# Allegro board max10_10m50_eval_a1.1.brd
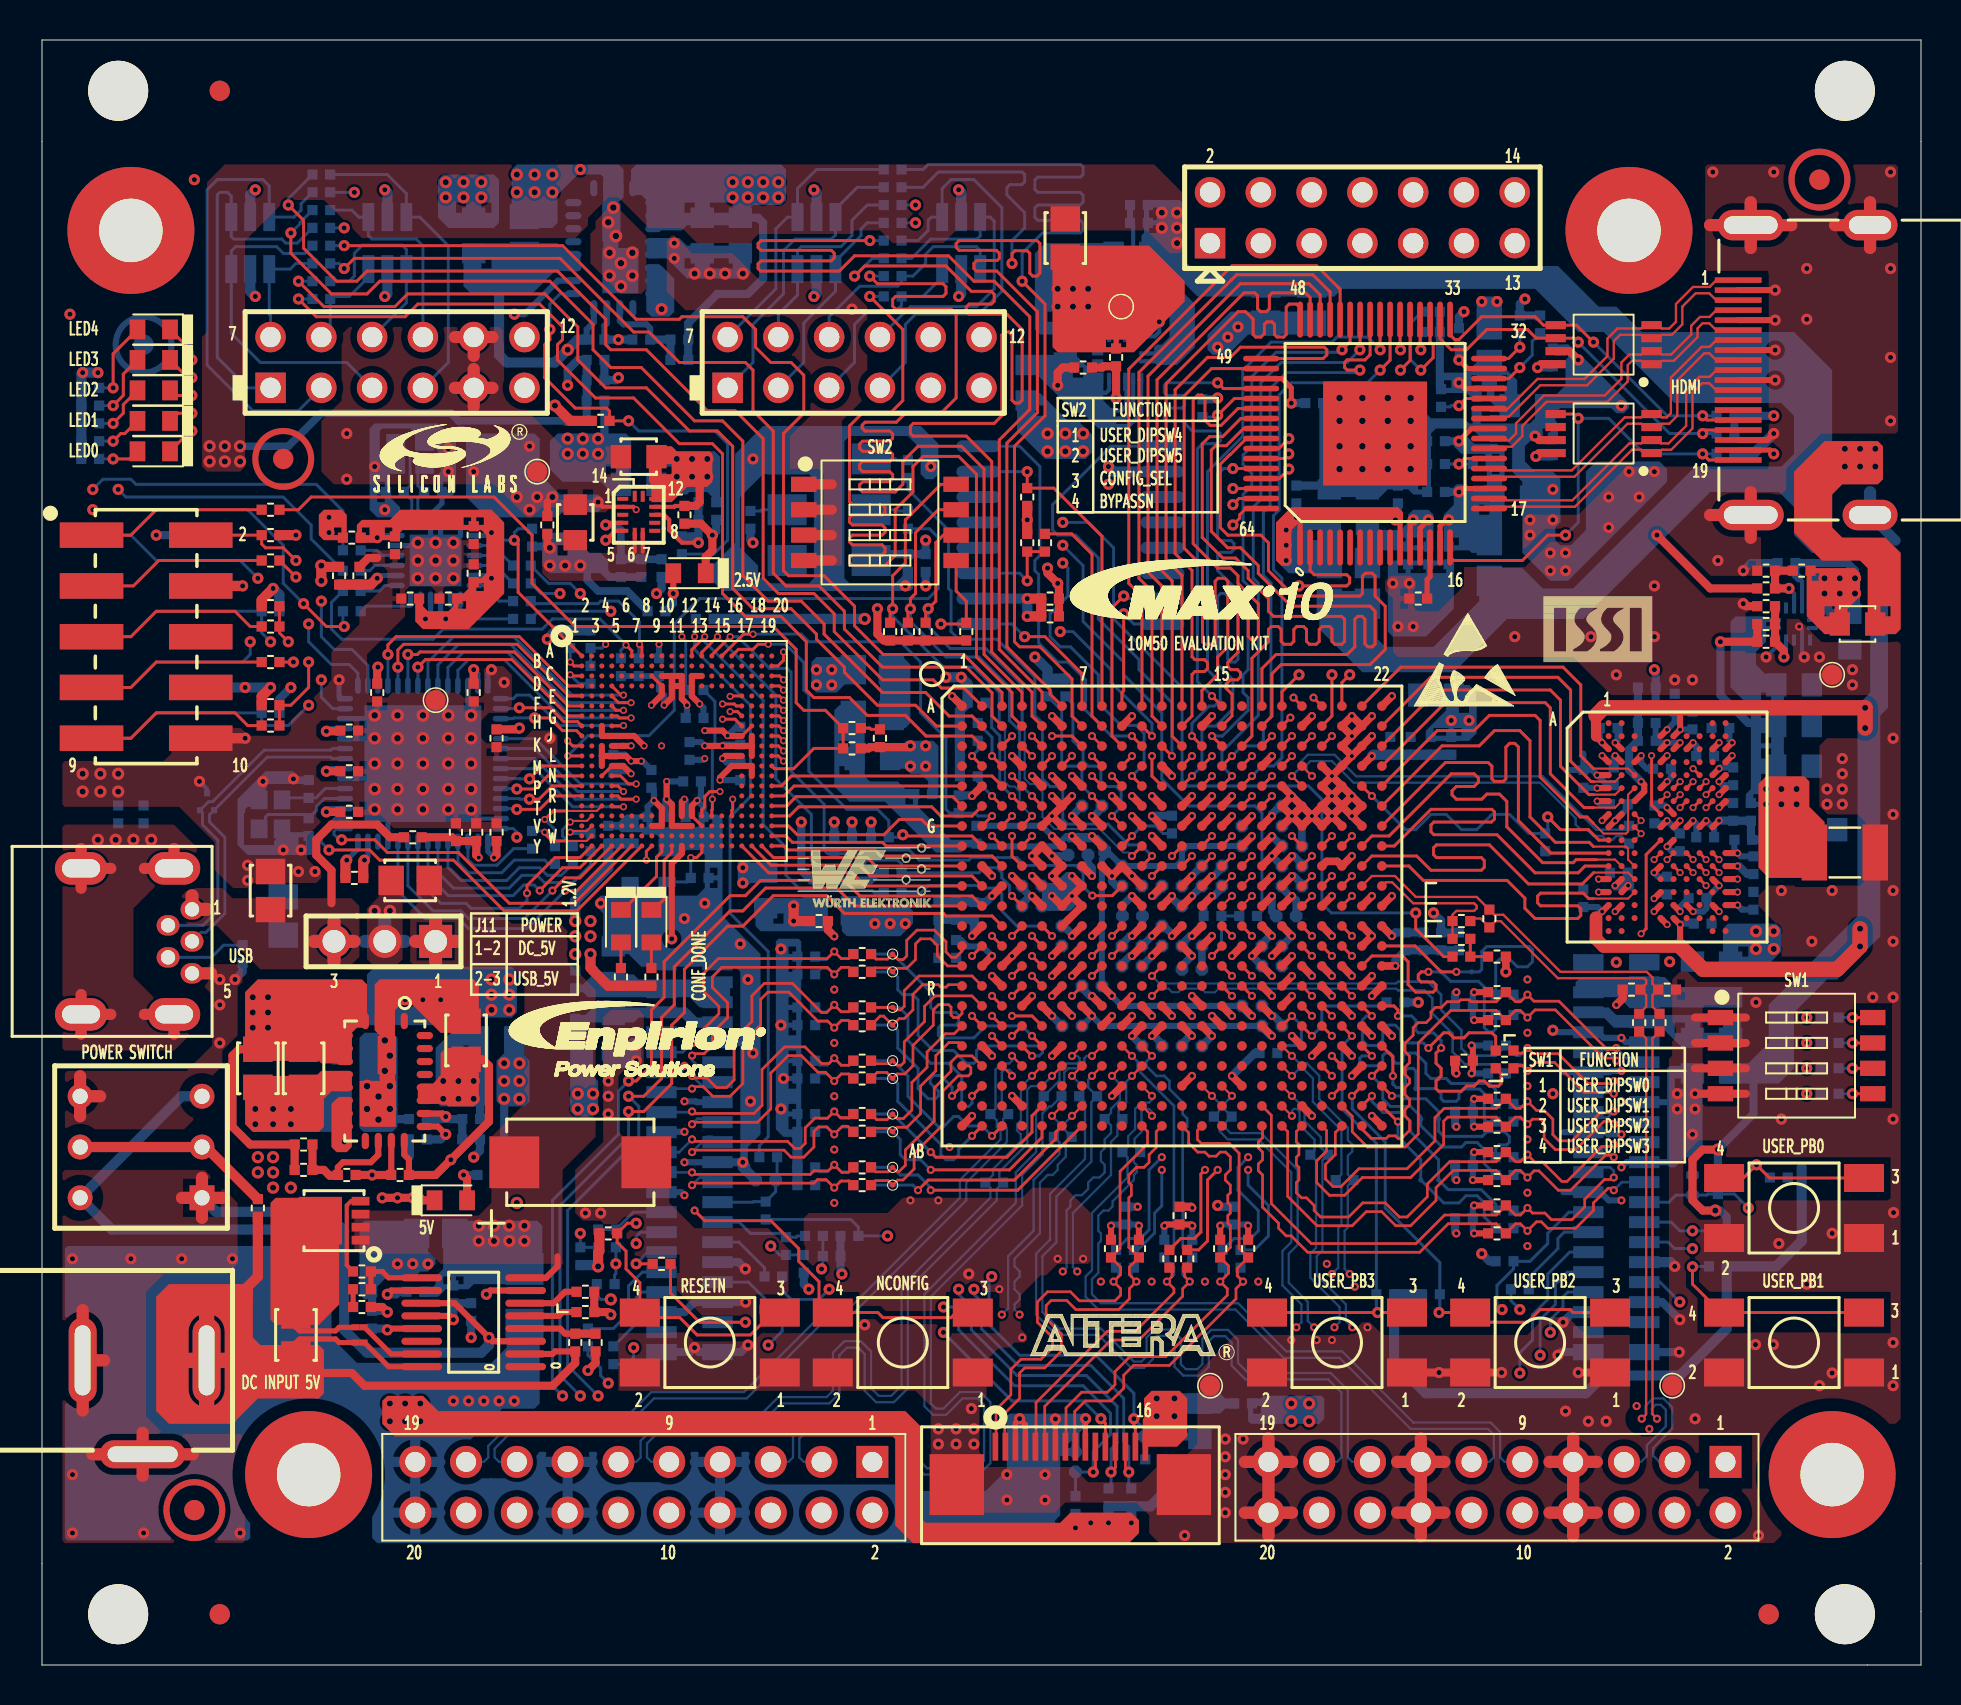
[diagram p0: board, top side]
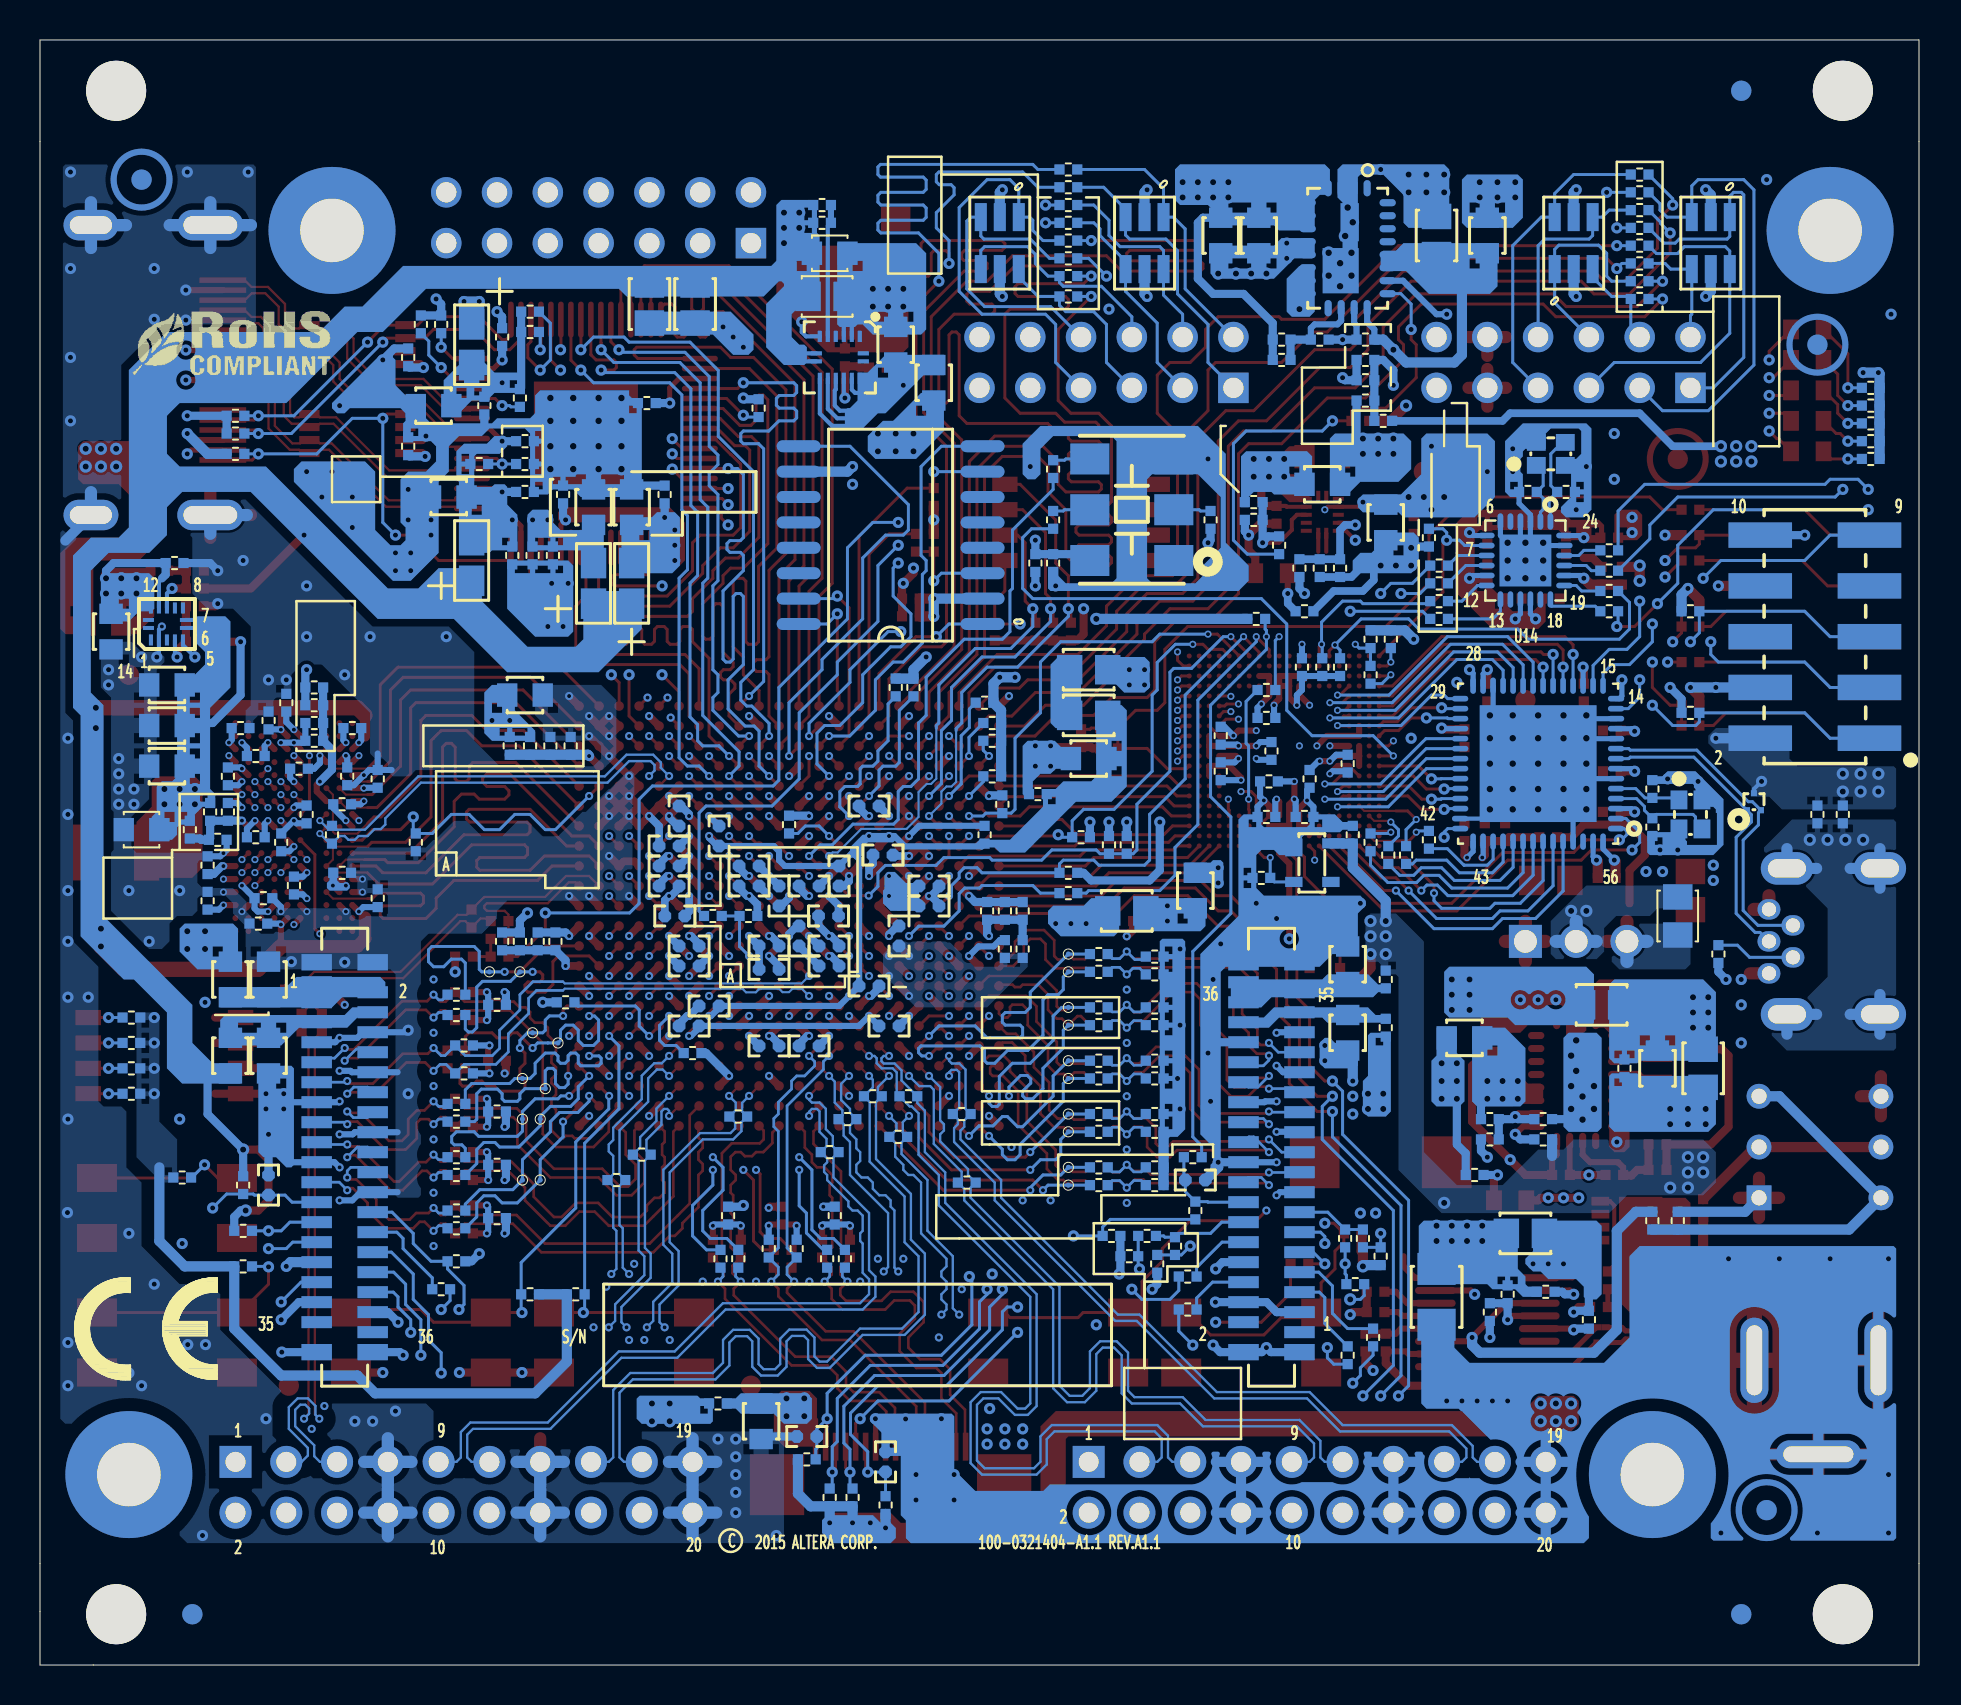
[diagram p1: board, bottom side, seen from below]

Outline 93.98 x 81.28 mm; copper layers: TOP, GND02, VCC03, ART04, GND05, BOTTOM. Coordinates in mm from the lower left corner of the outline.
Outline path: 0,81.28 0,0 93.98,0 93.98,81.28 0,81.28

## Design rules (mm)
net group DIFFPAIR48: nets USER_CLKIN_IO_N USER_CLKIN_IO_P
net group DP_FX2_D_: nets FX2_D_N FX2_D_P
net group MIPI_TX_CLKN: nets MIPI_TX_CLK_HS_N MIPI_TX_CLKN
net group MIPI_TX_CLKP: nets MIPI_TX_CLK_HS_P MIPI_TX_CLKP
net group MIPI_TX_DATA1N: nets MIPI_TX_DATA1N MIPI_TX_DATA_HS_N1
net group MIPI_TX_DATA1P: nets MIPI_TX_DATA1P MIPI_TX_DATA_HS_P1
net group MIPI_TX_DATA2N: nets MIPI_TX_DATA2N MIPI_TX_DATA_HS_N2
net group MIPI_TX_DATA2P: nets MIPI_TX_DATA2P MIPI_TX_DATA_HS_P2
net group MIPI_TX_DATA3N: nets MIPI_TX_DATA3N MIPI_TX_DATA_HS_N3
net group MIPI_TX_DATA3P: nets MIPI_TX_DATA3P MIPI_TX_DATA_HS_P3
net group MIPI_TX_DATA4N: nets MIPI_TX_DATA4N MIPI_TX_DATA_HS_N4
net group MIPI_TX_DATA4P: nets MIPI_TX_DATA4P MIPI_TX_DATA_HS_P4
net group OV10640_HS: nets OV10640_CLK_HS_N OV10640_CLK_HS_P
net group PMODA_D0: nets PMODA_D0 PMODA_IO0
net group PMODA_D1: nets PMODA_D1 PMODA_IO1
net group PMODA_D2: nets PMODA_D2 PMODA_IO2
net group PMODA_D3: nets PMODA_D3 PMODA_IO3
net group PMODA_D4: nets PMODA_D4 PMODA_IO4
net group PMODA_D5: nets PMODA_D5 PMODA_IO5
net group PMODA_D6: nets PMODA_D6 PMODA_IO6
net group PMODA_D7: nets PMODA_D7 PMODA_IO7
net group PMODB_D0: nets PMODB_D0 PMODB_IO0
net group PMODB_D1: nets PMODB_D1 PMODB_IO1
net group PMODB_D2: nets PMODB_D2 PMODB_IO2
net group PMODB_D3: nets PMODB_D3 PMODB_IO3
net group PMODB_D4: nets PMODB_D4 PMODB_IO4
net group PMODB_D5: nets PMODB_D5 PMODB_IO5
net group PMODB_D6: nets PMODB_D6 PMODB_IO6
net group PMODB_D7: nets PMODB_D7 PMODB_IO7
net group LVDS: nets USER_CLKIN_N_MAX10 USER_CLKIN_P USER_CLKIN_P_MAX10
net group OV10640_LP: nets OV10640_CLK_LP_N
net group TMDS: nets TMDS_CLK_N
net group VCC-GND: nets 1.2V_CORE 1.2V_CORE_SENSE 1.2V_VCCIO 3.3V_OV5640 5V 5V_MONITOR 5V_R1.2CORE 5V_R1.2VCCIO 5V_R2.5 5V_R3.3
nets with their own width: min track width 0.203; nets GND
nets with their own width: min track width 0.508; nets 3.3V

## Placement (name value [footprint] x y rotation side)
C1  0.1uF  [0402]  46.61 37.72 0 bottom
C3  0.1uF  [0402]  45.72 37.72 0 bottom
C4  0.1uF  [0402]  69.98 36.2 180 bottom
C6  0.1uF  [0402]  69.47 45.97 180 bottom
C8  0.1uF  [0402]  68.2 36.2 0 bottom
C9  0.1uF  [0402]  67.44 45.97 0 bottom
C10  0.1uF  [0402]  80.26 46.23 270 bottom
C11  0.1uF  [0402]  84.58 42.67 0 bottom
C13  10uF  [0603]  69.72 48.51 180 bottom
C14  4.7UF  [0402]  85.6 38.23 0 bottom
C15  0.1uF  [0402]  85.6 40 0 bottom
C16  0.1uF  [0402]  82.8 38.35 90 bottom
C17  0.1uF  [0402]  80.64 42.55 180 bottom
C18  22nF  [0402]  81.66 48.13 0 bottom
C19  22nF  [0402]  78.61 44.45 180 bottom
C20  0.01uF  [0402]  81.28 38.99 0 bottom
C21  0.01uF  [0402]  83.19 45.47 270 bottom
C22  4.7nF  [0402]  83.19 41.4 270 bottom
C23  4.7nF  [0402]  78.87 43.05 270 bottom
C24  2200pF  [0402]  78.87 39.62 90 bottom
C25  2200pF  [0402]  81.92 41.15 0 bottom
C26  4.7UF  [0402]  82.55 47.24 0 bottom
C27  0.1uF  [0402]  78.36 46.86 270 bottom
C28  DNI  [C0402_BGA]  36.2 24.26 180 bottom
C29  DNI  [0603]  28.57 31.62 270 bottom
C30  DNI  [0603]  28.57 35.05 90 bottom
C31  100 pF  [0402]  71.12 30.23 270 top
C32  100 pF  [0402]  71.12 25.02 90 bottom
C33  100 pF  [0402]  71.12 33.02 90 bottom
C34  100 pF  [0402]  71.12 22.35 90 bottom
C35  100 pF  [0402]  71.12 27.69 90 bottom
C36  DNI  [C0402_BGA]  82.55 24 90 bottom
C37  100 pF  [0402]  56.9 22.48 180 top
C38  DNI  [C0402_BGA]  51.69 10.16 90 bottom
C39  DNI  [C0402_BGA]  55.63 11.43 0 bottom
C40  100 pF  [0402]  59.56 22.48 0 bottom
C41  100 pF  [0402]  54.23 22.48 0 bottom
C42  0.1uF  [0402]  75.56 60.96 0 bottom
C43  0.1uF  [0402]  75.56 65.41 0 bottom
C44  10uF  [0603]  64.39 57.91 90 bottom
C45  0.1uF  [0402]  62.74 58.55 0 bottom
C46  0.1uF  [0402]  63.63 63.12 270 bottom
C47  0.1uF  [0402]  67.82 58.55 0 bottom
C48  0.1uF  [0402]  70.87 66.42 0 bottom
C49  10uF  [0603]  66.29 57.91 90 bottom
C50  0.1uF  [0402]  68.33 55.5 180 bottom
C51  0.1uF  [0402]  69.34 55.5 180 bottom
C52  10uF  [0603]  73.53 58.42 0 bottom
C53  0.1uF  [0402]  70.36 55.5 180 bottom
C54  0.1uF  [0402]  69.72 58.67 90 bottom
C55  0.1uF  [0402]  69.72 61.21 90 bottom
C56  10uF  [0603]  74.3 62.99 0 bottom
C57  0.1uF  [0402]  71.75 62.99 180 bottom
C58  0.1uF  [0402]  28.32 41.53 180 bottom
C59  4.7nF  [0402]  5.08 42.55 0 bottom
C60  12pF  [0402]  13.34 43.81 0 bottom
C61  12pF  [0402]  13.34 41.91 180 bottom
C62  0.1uF  [0402]  21.72 41.66 180 top
C63  0.1uF  [0402]  15.62 39.37 270 top
C64  0.1uF  [0402]  16.76 48.64 0 top
C65  0.1uF  [0402]  21.59 48.64 0 top
C66  0.1uF  [0402]  15.37 42.67 90 top
C67  0.1uF  [0402]  15.37 44.7 90 top
C68  0.1uF  [0402]  22.73 46.35 0 top
C69  0.1uF  [0402]  22.73 41.66 180 top
C70  0.1uF  [0402]  15.37 46.74 90 top
C71  DNI  [0402]  41.91 46.35 0 top
C72  0.1uF  [0402]  30.86 49.91 0 bottom
C73  0.1uF  [0402]  34.92 44.7 180 bottom
C74  0.1uF  [0402]  32.38 45.72 180 bottom
C75  0.1uF  [0402]  32.51 44.2 270 bottom
C76  0.1uF  [0402]  32.64 47.37 270 bottom
C77  0.1uF  [0402]  32.64 42.42 270 bottom
C78  0.1uF  [0402]  30.48 44.32 180 bottom
C79  0.1uF  [0402]  28.57 45.09 180 bottom
C80  0.1uF  [0402]  30.73 42.42 90 bottom
C81  0.1uF  [0402]  34.92 46.48 0 bottom
C82  0.1uF  [0402]  17.65 56.01 0 top
C83  0.1uF  [0402]  18.41 53.34 270 top
C84  0.1uF  [0402]  21.59 56.52 0 top
C85  0.1uF  [0402]  21.59 54.61 180 top
C86  0.1uF  [0402]  20.32 53.34 270 top
C87  DNI  [0402]  17.65 58.67 270 bottom
C88  0.1uF  [0402]  15.88 54.48 180 top
C89  DNI  [0402]  19.56 58.67 90 bottom
C90  22uF  [0805]  24.13 71.5 90 bottom
C91  6.8pF  [0402]  31.88 66.29 90 bottom
C92  22uF  [0603]  34.92 71.5 270 bottom
C93  22uF  [0603]  33.02 71.5 270 bottom
C94  150uF  [7343P]  26.92 25.15 0 top
C95  22uF  [1206]  24.13 18.41 90 bottom
C96  1.0UF  [0402]  27.69 66.29 270 bottom
C97  0.1uF  [0402]  27.18 17.65 90 top
C98  0.01uF  [0402]  16 17.91 270 top
C99  0.1uF  [0402]  27.18 18.67 90 top
C104  2.2uF  [0603]  51.18 66.04 90 bottom
C105  DNI  [0402]  54.86 72.14 90 bottom
C106  10uF  [0805]  54.61 68.45 180 bottom
C107  10uF  [0603]  54.48 70.61 180 bottom
C108  10uF  [0603]  41.53 45.34 0 bottom
C109  0.1uF  [0402]  44.07 43.56 270 bottom
C111  22uF  [0805]  21.21 31.24 90 top
C112  15pF  [0402]  13.08 24.77 270 top
C113  47uF  [0805]  13.08 29.84 270 top
C114  47uF  [0805]  10.79 29.84 270 top
C115  2.2uF  [0603]  90.42 51.69 270 bottom
C116  DNI  [0805]  10.79 29.84 270 bottom
C118  10uF  [0603]  87.63 49.02 0 bottom
C119  DNI  [0402]  86.23 54.74 270 top
C120  1.0UF  [0402]  17.91 24.51 270 top
C121  10uF  [0603]  36.2 38.73 90 bottom
C122  0.1uF  [0402]  38.86 37.21 90 top
C124  0.1uF  [C0402_BGA]  52.51 33.97 0 bottom
C144  0.1uF  [C0402_BGA]  57.51 30.97 180 bottom
C145  0.1uF  [C0402_BGA]  51.51 31.97 0 bottom
C146  0.1uF  [C0402_BGA]  52.51 42.97 180 bottom
C147  0.1uF  [C0402_BGA]  62.01 42.47 90 bottom
C148  0.1uF  [C0402_BGA]  61.51 31.97 180 bottom
C149  0.1uF  [C0402_BGA]  61.51 34.97 180 bottom
C155  0.1uF  [C0402_BGA]  49.51 38.97 0 bottom
C156  0.1uF  [C0402_BGA]  49.51 37.97 0 bottom
C169  4.7UF  [0402]  50.42 52.45 270 top
C170  0.1uF  [0402]  50.42 53.34 90 top
C171  10uF  [0603]  82.55 30.48 270 bottom
C172  10uF  [0603]  82.55 34.29 90 bottom
C173  10uF  [0603]  57.91 12.19 270 bottom
C174  DNI  [0402]  18.8 27.3 90 bottom
C175  DNI  [0402]  33.27 57.28 270 bottom
C176  DNI  [0402]  53.72 65.41 180 top
C194  1.0UF  [C0402_BGA]  61.51 35.97 180 bottom
C196  4.7uF  [C0402_BGA]  51.01 36.46 90 bottom
C197  0.22uF  [0402]  45.72 35.81 0 bottom
C206  0.1uF  [C0402_BGA]  60.01 41.47 270 bottom
C207  DNI  [0402]  27.69 65.28 270 bottom
C208  5 pF  [0402]  86.23 52.07 270 top
C209  2.2uF  [0603]  87.63 46.99 0 bottom
C210  0.1uF  [0402]  87.25 55.12 270 bottom
C211  2.2uF  [0603]  26.67 57.15 90 bottom
C212  0.1uF  [0402]  32.13 57.53 180 top
C213  10uF  [0603]  26.67 57.15 90 top
C215  2.2uF  [0603]  29.84 60.44 180 top
C216  5 pF  [0402]  29.97 54.86 180 bottom
C217  DNI  [0805]  61.21 68.07 270 bottom
C218  DNI  [0805]  63.5 68.07 270 bottom
C219  47uF  [0805]  51.18 71.37 270 top
C220  47uF  [0805]  11.43 38.73 90 top
C221  1.0UF  [C0402_BGA]  57.51 34.8 0 bottom
C222  1.0UF  [C0402_BGA]  54.54 37.46 0 bottom
C223  1.0UF  [C0402_BGA]  51.82 40.51 180 bottom
C224  0.1uF  [C0402_BGA]  56.01 36.47 90 bottom
C225  0.1uF  [C0402_BGA]  54.51 34.97 180 bottom
C226  0.1uF  [C0402_BGA]  57.01 38.47 270 bottom
C227  0.1uF  [C0402_BGA]  55.51 38.97 0 bottom
C228  0.1uF  [C0402_BGA]  54.51 35.97 0 bottom
C229  0.1uF  [C0402_BGA]  57.51 35.97 180 bottom
C230  0.1uF  [C0402_BGA]  58.51 39.97 0 bottom
C231  0.1uF  [C0402_BGA]  58.51 38.97 180 bottom
C232  DNI  [1210]  90.17 40.64 0 top
C233  0.1uF  [C0402_BGA]  62.51 40.97 180 bottom
C234  0.1uF  [C0402_BGA]  62.23 37.46 180 bottom
C235  0.1uF  [C0402_BGA]  62.51 39.97 0 bottom
C236  0.1uF  [C0402_BGA]  62.51 38.97 0 bottom
C237  0.1uF  [C0402_BGA]  60.51 32.97 180 bottom
C238  0.1uF  [C0402_BGA]  54.01 39.47 90 bottom
C239  0.1uF  [C0402_BGA]  55.51 30.97 0 bottom
C240  0.1uF  [0402]  43.31 55.12 180 bottom
C241  0.1uF  [0402]  80.26 48.01 90 bottom
C242  0.1uF  [0402]  86.49 41.78 180 bottom
C243  0.1uF  [0402]  77.09 38.35 0 bottom
C244  0.1uF  [0402]  83.95 46.86 90 bottom
C245  0.1uF  [0402]  84.58 44.45 180 bottom
C246  0.1uF  [0402]  77.09 44.32 0 bottom
C247  0.1uF  [0402]  83.06 37.08 270 bottom
C248  DNI  [0603]  13.08 29.84 270 bottom
C249  DNI  [0402]  14.73 29.84 180 bottom
C250  2.2uF  [0603]  87.63 44.96 0 bottom
C251  2.2uF  [0402]  25.27 57.02 180 top
D1  82401646  [WURTH_MSOP8]  78.11 61.59 180 top
D2  82401646  [WURTH_MSOP8]  78.11 66.04 180 top
D3  GREEN_LED  [LED_0603]  5.59 60.71 0 top
D4  GREEN_LED  [LED_0603]  5.59 62.23 0 top
D5  GREEN_LED  [LED_0603]  5.59 63.75 0 top
D6  GREEN_LED  [LED_0603]  5.59 65.28 0 top
D7  GREEN_LED  [LED_0603]  5.59 66.8 0 top
D8  GREEN_LED  [LED_0603]  30.48 36.96 90 top
D9  YELLOW_LED  [LED_0603]  20.45 23.24 180 top
D10  YELLOW_LED  [LED_0603]  32.38 54.61 0 top
D11  YELLOW_LED  [LED_0603]  28.96 36.96 90 top
J1  FFC_CONN_1x36  [52559-3652]  32.38 25.4 90 bottom
J2  FFC_CONN_1x36  [52559-3652]  78.74 25.4 270 bottom
J3  FFC CONN 1x16  [68711614522]  51.44 10.92 0 top
J4  685119134923  [HDMI-19PIN]  84.84 64.77 180 top
J5  USB MINI-B  [WURTH_USB_MINI-B]  6.6 36.2 270 top
J6  DNI  [HDR2X5_100MIL_SMT]  5.21 53.98 0 bottom
J7  2X5_100mil  [HDR2X5_100MIL_SMT]  5.21 48.89 0 top
J8  2x6 PMOD Connector  [HDR2X6_100MIL]  34.29 63.88 90 top
J9  2x6 PMOD Connector  [HDR2X6_100MIL]  11.43 63.88 90 top
J10  DC Input Jack 2.0 mm  [JACK-DC_2MM]  2.03 15.24 90 top
J11  HEADER, 1x3-PIN  [CONN_TSW_103_07_L_S]  19.68 36.2 180 top
J12  Header 2x10 (DNI)  [10-89-1201]  84.2 10.16 180 top
J13  Header 2x10 (DNI)  [10-89-1201]  41.53 10.16 180 top
J14  Header 2x7 (DNI)  [10-89-1141]  58.42 71.12 90 top
L1  10uH  [0806]  64.39 54.1 0 bottom
L2  10uH  [0806]  66.29 54.1 0 bottom
L3  10uH  [0806]  72.39 55.24 0 bottom
L4  10uH  [0806]  72.39 66.04 180 bottom
L5  BLM15AG221SN1  [0402]  15.49 56.39 270 top
L6  BLM15AG221SN1  [0402]  14.86 54.48 180 top
L7  742792022  [0805]  41.53 47.5 180 bottom
L8  742792022  [0805]  39.62 37.72 180 bottom
L9  BLM15AG221SN1  [0402]  44.2 55.12 0 bottom
NOREF  -  [unnamed]  8.89 2.54 0 top
NOREF#2  -  [unnamed]  7.62 7.75 0 top
NOREF#3  -  [unnamed#2]  79.38 71.75 0 top
NOREF#4  -  [unnamed#2]  90.17 2.54 0 top
NOREF#5  -  [unnamed#2]  89.53 9.53 0 top
NOREF#6  -  [unnamed#2]  90.17 78.74 0 top
NOREF#7  -  [unnamed#2]  4.45 71.75 0 top
NOREF#8  -  [unnamed]  8.89 78.74 0 top
NOREF#9  -  [unnamed#2]  3.81 2.54 0 top
NOREF#10  -  [unnamed]  86.36 2.54 0 top
NOREF#11  -  [unnamed#2]  3.81 78.74 0 top
NOREF#12  -  [unnamed]  12.06 60.32 0 top
NOREF#13  -  [unnamed#2]  13.34 9.53 0 top
NOREF#14  -  [unnamed]  88.9 74.3 0 top
NOREF#15  -  [unnamed]  5.08 66.04 180 bottom
NOREF#16  -  [unnamed]  86.36 2.54 180 bottom
NOREF#17  -  [unnamed]  7.62 7.75 180 bottom
NOREF#18  -  [unnamed]  8.89 2.54 180 bottom
NOREF#19  -  [unnamed]  88.9 74.3 180 bottom
NOREF#20  -  [unnamed]  8.89 78.74 180 bottom
R1  1.00k  [0402]  44.83 35.81 180 bottom
R2  1.00k  [0402]  44.83 37.72 180 bottom
R7  47.5  [0402]  67.69 33.15 90 bottom
R8  47.5  [0402]  61.34 30.61 270 bottom
R9  1.00k  [0402]  70.87 36.2 0 bottom
R10  1.00k  [0402]  70.48 45.97 0 bottom
R11  1.00k  [0402]  69.09 36.2 180 bottom
R12  1.00k  [0402]  68.45 45.97 180 bottom
R17  200  [0402]  60.33 37.46 270 bottom
R18  100.0  [0402]  58.55 37.46 270 bottom
R19  200  [0402]  70.99 35.43 270 top
R20  100.0  [0402]  72.77 35.43 270 top
R21  10.0K  [0402]  39.62 41.02 180 bottom
R22  DNI  [0402]  40.51 41.02 180 bottom
R23  1.00k  [0402]  45.85 43.05 180 bottom
R24  10.0K  [0402]  41.91 41.4 270 bottom
R25  10.0K  [0402]  42.55 39.62 270 bottom
R27  10.0K  [0402]  51.18 48.89 180 bottom
R28  10.0K  [0402]  50.29 48.89 180 bottom
R29  1.00k  [0402]  80.26 48.89 270 bottom
R30  1.00k  [0402]  85.47 42.67 0 bottom
R31  4.7k  [0402]  75.18 41.15 0 bottom
R32  1.00k  [0402]  80.26 47.12 90 bottom
R33  DNI  [0402]  79.38 41.53 180 bottom
R34  1.00k  [0402]  85.09 41.27 270 bottom
R35  240  [0402]  81.03 44.83 270 bottom
R36  100.0  [0402]  41.02 26.67 270 bottom
R37  100.0  [0402]  41.02 32.89 270 bottom
R38  100.0  [0402]  38.23 32.89 90 bottom
R39  100.0  [0402]  38.23 26.67 90 bottom
R40  150  [0402]  41.02 26.67 90 top
R41  150  [0402]  41.02 32.89 90 top
R42  150  [0402]  41.02 32 90 top
R43  100.0  [0402]  38.23 32 270 bottom
R44  150  [0402]  41.02 27.56 90 top
R45  100.0  [0402]  38.23 27.56 270 bottom
R46  100.0  [0402]  41.02 27.56 270 bottom
R47  100.0  [0402]  41.02 32 270 bottom
R48  100.0  [0402]  41.02 35.56 270 bottom
R49  100.0  [0402]  41.02 24.89 270 bottom
R50  150  [0402]  41.02 35.56 90 top
R51  100.0  [0402]  38.23 35.43 90 bottom
R52  100.0  [0402]  38.23 24.89 90 bottom
R53  150  [0402]  41.02 24.89 90 top
R54  150  [0402]  41.02 34.67 90 top
R55  100.0  [0402]  38.23 34.54 270 bottom
R56  150  [0402]  41.02 24 90 top
R57  100.0  [0402]  38.23 24 270 bottom
R58  100.0  [0402]  41.02 34.67 270 bottom
R59  100.0  [0402]  41.02 24 270 bottom
R60  100.0  [0402]  41.02 30.23 270 bottom
R61  DNI  [0402]  26.67 34.29 180 bottom
R62  150  [0402]  41.02 30.23 90 top
R63  100.0  [0402]  38.23 30.23 90 bottom
R64  DNI  [0402]  26.67 31.88 0 bottom
R65  150  [0402]  41.02 29.34 90 top
R66  100.0  [0402]  38.23 29.34 270 bottom
R67  100.0  [0402]  41.02 29.34 90 bottom
R68  DNI  [0402]  39.5 20.45 90 bottom
R71  100.0  [0402]  73.15 30.73 270 top
R72  100.0  [0402]  73.15 25.4 90 bottom
R73  200  [0402]  72.77 30.99 270 bottom
R74  200  [0402]  72.77 25.65 90 top
R75  200  [0402]  72.77 29.59 90 bottom
R76  200  [0402]  72.77 24.26 270 top
R77  100.0  [0402]  73.15 29.84 270 top
R78  100.0  [0402]  73.15 24.51 90 bottom
R79  100.0  [0402]  73.15 32.51 90 bottom
R80  100.0  [0402]  73.15 22.73 90 bottom
R81  200  [0402]  72.77 32.26 90 top
R82  200  [0402]  72.77 22.99 90 top
R83  200  [0402]  72.77 33.66 270 top
R84  200  [0402]  72.77 21.59 270 top
R85  100.0  [0402]  73.15 21.84 90 bottom
R86  100.0  [0402]  73.15 33.53 90 bottom
R87  100.0  [0402]  73.15 28.07 90 bottom
R88  200  [0402]  72.77 28.32 90 top
R89  2.0K  [0402]  73.15 20.19 270 bottom
R90  200  [0402]  72.77 26.92 270 top
R91  2.0K  [0402]  83.82 24 180 bottom
R92  2.0K  [0402]  83.82 21.72 90 bottom
R93  100.0  [0402]  73.15 27.18 90 bottom
R94  DNI  [0402]  73.91 18.8 90 bottom
R95  100.0  [0402]  57.28 20.32 180 top
R96  200  [0402]  57.53 20.83 180 bottom
R97  200  [0402]  56.13 20.83 0 bottom
R98  DNI  [0402]  51.69 8 0 bottom
R99  DNI  [0402]  55.63 10.29 90 bottom
R100  DNI  [0402]  54.48 8.38 0 bottom
R101  DNI  [0402]  53.34 8.38 0 bottom
R102  100.0  [0402]  56.39 20.32 180 top
R103  100.0  [0402]  59.94 20.32 0 bottom
R104  200  [0402]  60.33 20.83 0 top
R105  200  [0402]  58.93 20.83 180 top
R106  100.0  [0402]  59.05 20.32 0 bottom
R107  100.0  [0402]  54.61 20.32 0 bottom
R108  200  [0402]  54.86 20.83 0 top
R109  200  [0402]  53.47 20.83 180 top
R110  100.0  [0402]  53.72 20.32 0 bottom
R111  0  [0402]  73.91 67.06 180 bottom
R112  0  [0402]  74.93 67.06 180 bottom
R113  DNI  [0402]  58.04 62.86 180 bottom
R114  2.0K  [0402]  84.2 61.59 270 bottom
R115  2.0K  [0402]  84.2 62.48 270 bottom
R116  887  [0402]  68.83 53.34 90 top
R117  10.0K  [0402]  84.2 60.58 270 bottom
R118  2.0K  [0402]  69.72 60.07 90 bottom
R119  DNI  [0402]  72.01 60.07 90 bottom
R120  2.0K  [0402]  69.47 66.67 270 bottom
R121  2.0K  [0402]  69.47 67.69 270 bottom
R122  2.0K  [0402]  69.98 63.37 0 bottom
R123  0  [0402]  27.43 49.53 180 bottom
R124  DNI  [0402]  10.03 35.56 180 bottom
R125  1M  [0402]  3.81 42.55 180 bottom
R126  100K  [0402]  32.89 39.37 270 bottom
R127  2.0K  [0402]  26.42 51.31 180 bottom
R128  2.0K  [0402]  27.43 51.31 180 bottom
R129  0  [0402]  24.51 41.27 180 bottom
R130  0  [0402]  26.54 40.51 180 bottom
R131  0  [0402]  27.43 41.15 180 bottom
R132  0  [0402]  25.65 40.51 180 bottom
R133  10.0K  [0402]  18.54 41.4 90 top
R134  20.0K  [0402]  20.7 41.66 0 top
R135  1.00k  [0402]  11.43 47.62 90 bottom
R136  1.00k  [0402]  11.43 52.7 90 bottom
R137  4.7k  [0402]  28.96 49.91 0 bottom
R138  1.00k  [0402]  46.35 44.45 270 bottom
R139  4.7k  [0402]  29.84 49.91 0 bottom
R140  1.00k  [0402]  46.35 46.23 270 bottom
R141  1.00k  [0402]  46.35 47.12 270 bottom
R142  1.00k  [0402]  46.74 48.13 270 bottom
R143  DNI  [0402]  40.51 46.86 90 top
R144  1.00k  [0402]  40.51 45.85 270 top
R145  1.00k  [0402]  11.43 52.96 270 top
R146  1.00k  [0402]  11.43 48.01 270 top
R147  1.00k  [0402]  11.43 56.52 270 top
R148  22.0  [0402]  11.43 57.78 90 top
R149  22.0  [0402]  11.43 55.24 90 top
R150  22.0  [0402]  11.43 51.94 90 top
R151  22.0  [0402]  11.43 50.16 90 top
R152  22.0  [0402]  11.43 46.99 90 top
R153  DNI  [0402]  54.48 25.65 270 bottom
R154  DNI  [0402]  52.32 28.45 270 bottom
R155  DNI  [0402]  63.88 25.53 270 bottom
R156  200  [0402]  42.55 73.91 90 bottom
R157  200  [0402]  42.55 72.14 90 bottom
R158  200  [0402]  42.55 74.8 270 bottom
R159  200  [0402]  42.55 73.02 270 bottom
R160  200  [0402]  42.55 68.45 270 bottom
R161  200  [0402]  42.55 69.47 90 bottom
R162  DNI  [0402]  59.05 27.43 270 bottom
R163  200  [0402]  42.55 71.25 270 bottom
R164  200  [0402]  42.55 70.36 90 bottom
R165  DNI  [0402]  53.59 27.3 270 bottom
R166  DNI  [0402]  50.55 28.45 270 bottom
R167  DNI  [0402]  47.62 24.13 270 bottom
R168  DNI  [0402]  47.88 27.56 270 bottom
R169  DNI  [0402]  51.05 26.42 270 bottom
R170  DNI  [0402]  65.15 24.26 270 bottom
R171  200  [0402]  13.97 71.88 90 bottom
R172  200  [0402]  13.97 70.1 270 bottom
R173  200  [0402]  13.97 73.66 90 bottom
R174  200  [0402]  13.97 68.33 90 bottom
R175  200  [0402]  13.97 70.99 90 bottom
R176  200  [0402]  13.97 69.22 90 bottom
R177  200  [0402]  13.97 74.55 270 bottom
R178  200  [0402]  13.97 72.77 90 bottom
R179  2.0K  [0402]  79.88 32.13 180 top
R180  1.00k  [0402]  79.5 33.78 90 top
R181  10.0K  [0402]  89.41 32.38 270 bottom
R182  10.0K  [0402]  89.41 31.12 270 bottom
R183  150  [0402]  2.41 60.32 270 bottom
R184  10.0K  [0402]  89.41 29.84 270 bottom
R185  10.0K  [0402]  89.41 28.58 270 bottom
R186  150  [0402]  2.41 61.21 270 bottom
R187  150  [0402]  2.41 62.1 270 bottom
R188  150  [0402]  2.41 62.99 270 bottom
R189  10.0K  [0402]  42.42 51.69 180 top
R190  10.0K  [0402]  43.31 51.69 180 top
R191  10.0K  [0402]  44.2 51.69 180 top
R192  10.0K  [0402]  46.23 51.69 180 top
R193  150  [0402]  2.41 63.88 270 bottom
R194  390  [0402]  30.48 34.42 180 top
R195  10.0K  [0402]  69.47 18.54 270 bottom
R196  10.0K  [0402]  83.82 19.94 90 bottom
R198  10.0K  [0402]  67.18 18.54 90 bottom
R199  1.00k  [0402]  22.23 24.51 90 bottom
R200  150  [0402]  30.73 52.7 90 bottom
R202  10.0K  [0402]  86.87 24.38 90 bottom
R203  10.0K  [0402]  56.52 42.04 180 bottom
R204  10.0K  [0402]  28.32 21.59 90 top
R205  4.7k  [0402]  24.51 56.39 180 bottom
R206  22.0  [0402]  24 53.21 90 bottom
R207  0  [0402]  24 54.99 270 bottom
R208  0  [0402]  24 54.1 270 bottom
R209  22.0  [0402]  15.49 53.72 270 bottom
R210  0  [0402]  24 52.32 270 bottom
R211  0  [0402]  15.49 52.7 90 bottom
R212  DNI  [0402]  15.49 54.74 90 bottom
R213  0  [0402]  15.49 55.75 90 bottom
R214  1.00k  [0402]  35.43 57.28 0 bottom
R215  22.0  [0402]  43.31 59.82 180 bottom
R216  22.0  [0402]  43.31 57.28 180 bottom
R217  40.2K  [0402]  10.79 22.86 180 top
R221  20.0K  [0402]  12.06 22.23 180 bottom
R222  0.005  [0805]  12.7 16.51 270 top
R223  348K  [0402]  31.88 65.28 270 bottom
R224  69.8K  [0402]  26.67 16.13 0 top
R225  10  [0402]  16 19.69 90 top
R226  60.4K  [0402]  20.57 18.54 0 bottom
R227  10.0K  [0402]  18.67 18.67 270 bottom
R228  1K  [0805]  19.68 21.59 180 bottom
R229  78.7K  [0402]  29.97 66.29 270 bottom
R230  20.0K  [0402]  27.69 16.13 180 top
R231  1.00k  [0402]  16 18.8 90 top
R232  20.0K  [0402]  16.51 17.27 180 bottom
R233  20.0K  [0402]  21.46 17.65 0 bottom
R235  0  [0402]  54.86 73.02 90 bottom
R236  0.1  [0805]  41.53 49.78 0 bottom
R238  0.01  [0805]  15.88 33.02 0 bottom
R239  10.0K  [0402]  18.8 26.29 90 bottom
R240  348K  [0402]  13.08 26.03 270 top
R241  DNI  [0402]  86.23 53.85 270 top
R242  0  [0402]  88.01 54.74 90 top
R243  348K  [0402]  15.24 24.51 270 top
R244  2.0K  [0402]  49.28 56.13 0 top
R245  DNI  [0402]  49.28 58.42 180 top
R246  0  [0603]  84.45 30.48 90 bottom
R247  0  [0603]  84.45 34.29 270 bottom
R248  0  [0402]  60.07 13.08 270 bottom
R249  0  [0402]  32.64 48.77 270 bottom
R250  0  [0402]  50.16 56.13 180 top
R252  DNI  [0402]  21.46 27.3 270 bottom
R253  0  [0603]  22.73 31.37 180 bottom
R254  0  [0603]  90.81 52.07 180 top
R255  DNI  [0402]  33.27 58.17 270 bottom
R257  0  [0402]  52.07 64.9 90 top
R258  0  [0603]  49.28 64.14 90 bottom
R260  0  [0603]  21.59 71.5 270 bottom
R264  0  [0402]  13.34 22.23 0 bottom
R267  DNI  [0402]  46.74 41.53 180 bottom
R268  2.0K  [0402]  80.9 32.13 180 top
R269  1.00k  [0402]  81.28 33.78 270 top
R270  0  [0402]  70.99 36.32 270 top
R271  DNI  [0402]  70.99 37.21 270 top
R272  DNI  [0402]  72.39 37.34 0 top
R273  DNI  [0402]  36.58 19.43 90 bottom
R274  DNI  [0402]  30.99 20.07 270 top
R275  DNI  [0402]  27.3 16.38 0 bottom
R276  DNI  [0402]  36.58 17.78 90 bottom
R277  DNI  [0402]  28.57 15.49 0 bottom
R278  390  [0402]  28.96 34.42 180 top
R279  0  [0402]  26.8 62.23 90 bottom
R280  DNI  [0402]  27.69 63.25 270 bottom
R281  10.0K  [0402]  27.94 62.23 270 top
R282  0  [0402]  32 56.01 180 bottom
R283  0  [0402]  21.46 26.29 270 bottom
R284  DNI  [0402]  27.69 64.26 90 bottom
R285  200k  [0402]  86.23 51.18 270 top
R286  200k  [0402]  86.23 52.96 90 top
R289  0  [0603]  29.84 59.05 0 bottom
R290  200k  [0402]  28.96 54.86 180 bottom
R291  63.0K  [0402]  30.99 54.86 0 bottom
R292  DNI  [0805]  18.41 39.24 180 top
R293  DNI  [0805]  12.06 37.46 270 bottom
R294  DNI  [0402]  38.61 21.46 270 bottom
R302  DNI  [0402]  37.21 20.95 180 bottom
R303  DNI  [0402]  38.1 20.07 0 bottom
R304  DNI  [0402]  27.81 21.34 180 bottom
R305  DNI  [0402]  28.19 19.05 270 bottom
R306  DNI  [0402]  26.92 20.45 0 bottom
R307  DNI  [0402]  28.7 21.34 180 bottom
R308  DNI  [0402]  40.39 21.46 270 bottom
R309  DNI  [0402]  33.15 52.32 90 bottom
R312  DNI  [0402]  36.2 22.73 180 bottom
R313  DNI  [0402]  36.32 25.4 90 bottom
R314  22.0  [0402]  42.55 38.61 270 bottom
R315  51  [0603]  88.9 41.78 180 bottom
S1  PB Switch  [PUSHBUTTON_SMT]  87.63 22.86 180 top
S2  PB Switch  [PUSHBUTTON_SMT]  87.63 16.13 180 top
S3  PB Switch  [PUSHBUTTON_SMT]  74.93 16.13 180 top
S4  PB Switch  [PUSHBUTTON_SMT]  64.77 16.13 180 top
S6  PB Switch  [PUSHBUTTON_SMT]  43.05 16.13 180 top
S7  PB Switch  [PUSHBUTTON_SMT]  33.4 16.13 180 top
SW1  DIPSWITCH4  [DIPSWITCH_SMT_QUAD]  87.76 32.38 270 top
SW2  DIPSWITCH4  [DIPSWITCH_SMT_QUAD]  41.91 59.05 270 top
SW3  POWER SW  [SW-PUSH-8X8]  8 23.37 90 top
TP1  T POINT R  [TEST_PAD_SMT]  81.53 13.97 270 top
TP2  T POINT R  [TEST_PAD_SMT]  58.42 13.97 90 top
TP3  T POINT R  [TEST_PAD_SMT]  24.77 59.69 180 top
TP4  T POINT R  [TEST_PAD_SMT]  53.98 67.95 180 top
TP5  T POINT R  [TEST_PAD_SMT]  89.53 49.53 270 top
TP6  T POINT R  [TEST_PAD_SMT]  19.68 48.26 270 top
TP7  T POINT R  [TEST_PAD_SMT_10MIL]  42.55 32.89 180 bottom
TP8  T POINT R  [TEST_PAD_SMT_10MIL]  42.55 32.89 0 top
TP10  T POINT R  [TEST_PAD_SMT_10MIL]  42.55 32 0 top
TP11  T POINT R  [TEST_PAD_SMT_10MIL]  42.55 32 180 bottom
TP13  T POINT R  [TEST_PAD_SMT_10MIL]  42.55 35.56 180 bottom
TP14  T POINT R  [TEST_PAD_SMT_10MIL]  42.55 35.56 0 top
TP15  T POINT R  [TEST_PAD_SMT_10MIL]  42.55 34.67 0 top
TP16  T POINT R  [TEST_PAD_SMT_10MIL]  42.55 34.67 180 bottom
TP19  T POINT R  [TEST_PAD_SMT_10MIL]  42.55 30.23 180 bottom
TP20  T POINT R  [TEST_PAD_SMT_10MIL]  42.55 30.23 0 top
TP21  T POINT R  [TEST_PAD_SMT_10MIL]  42.55 29.34 0 top
TP22  T POINT R  [TEST_PAD_SMT_10MIL]  42.55 29.34 180 bottom
TP25  T POINT R  [TEST_PAD_SMT_10MIL]  42.55 26.67 180 bottom
TP26  T POINT R  [TEST_PAD_SMT_10MIL]  42.55 26.67 0 top
TP27  T POINT R  [TEST_PAD_SMT_10MIL]  42.55 27.56 0 top
TP28  T POINT R  [TEST_PAD_SMT_10MIL]  42.55 27.56 180 bottom
TP31  T POINT R  [TEST_PAD_SMT_10MIL]  42.55 24.89 180 bottom
TP32  T POINT R  [TEST_PAD_SMT_10MIL]  42.55 24.89 0 top
TP33  T POINT R  [TEST_PAD_SMT_10MIL]  42.55 24 0 top
TP34  T POINT R  [TEST_PAD_SMT_10MIL]  42.55 24 180 bottom
TP45  T POINT R  [TEST_PAD_SMT_10MIL]  69.98 34.67 180 bottom
TP48  T POINT R  [TEST_PAD_SMT_10MIL]  71.5 34.67 180 bottom
TP50  T POINT R  [TEST_PAD_SMT_10MIL]  69.85 29.34 180 bottom
TP54  T POINT R  [TEST_PAD_SMT_10MIL]  68.71 28.83 180 bottom
TP57  T POINT R  [TEST_PAD_SMT_10MIL]  69.85 27.3 180 bottom
TP60  T POINT R  [TEST_PAD_SMT_10MIL]  68.96 27.3 180 bottom
TP63  T POINT R  [TEST_PAD_SMT_10MIL]  69.85 24.26 180 bottom
TP66  T POINT R  [TEST_PAD_SMT_10MIL]  68.96 24.26 180 bottom
TP67  T POINT R  [TEST_PAD_SMT_10MIL]  68.07 31.12 180 bottom
TP68  T POINT R  [TEST_PAD_SMT_10MIL]  69.34 31.62 180 bottom
U1  10M50DAF484  [F484]  56.52 37.46 0 top
U2  LPDDR2_IS43LD16640A-3BL  [FBGA134]  81.28 41.91 0 top
U3  ADV7513BSWZ  [LQFP-64]  66.67 61.59 90 top
U4  EPM1270_M256FBGA  [M256]  31.75 45.72 0 top
U5  MAX811  [SOT-143]  30.35 40.13 180 bottom
U6  TPD2EUSB30  [DRT]  8.26 43.18 180 bottom
U7  CY7C68013A_QFN  [QFN56]  19.05 45.09 0 bottom
U8  824013  [SOT23-6L]  45.97 71.12 0 bottom
U9  824013  [SOT23-6L]  38.73 71.12 0 bottom
U10  824013  [SOT23-6L]  10.41 71.12 0 bottom
U11  824013  [SOT23-6L]  17.27 71.12 180 bottom
U14  Si5338C-CUSTOM  [QFN24]  19.68 55.24 270 bottom
U15  510MCA50M0000AAGR  [SI510]  39.37 57.78 90 bottom
U16  FDMC8878  [FDMC8878_VER2]  14.61 22.23 90 top
U17  EN5329QI  [EN5339QI]  28.57 70.87 270 bottom
U18  LTC4218CGN  [16-LEAD_PLASTIC_SSOP]  21.59 17.14 90 top
U19  -  [EP5348UI]  29.84 57.53 0 top
U20  EP5358HUI  [UQFN16]  53.98 65.41 270 bottom
U21  -  [EN5339QI]  17.14 29.21 270 top
U22  -  [EP5348UI]  87.63 52.07 90 bottom
U23  N25Q512A83GSF40F  [SO16_WIDE]  51.44 56.52 90 bottom
V1  SENSE_PAD  [SENSE]  15.88 16.13 270 top
V2  SENSE_PAD  [SENSE]  15.88 16.89 270 top
Y1  24.00MHz  [XTAL_FA-128]  11.43 42.55 270 bottom
Y2  25.00MHz  [XTAL_FA-128]  18.41 60.58 180 bottom

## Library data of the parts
C1 C3 C4 C6 C8-C11 C15-C17 C27 C31-C35 C37 C40-C43 C45-C48 C50 C51 C53-C55 C57 C58 C62-C86 C88 C91 C109 C122 C170 C197 C210 C212 C240-C247 = Cap 0.1UF +/-10% 10V 0402: Tolerance: TOL; User Part Number: PART#
C13 C29 C30 C44 C49 C52 C56 C95 C104 C106-C108 C113-C115 C118 C121 C171-C173 C209 C211 C213 C215 C217-C220 C248 C250 = CAP
C14 C26 C169 = Cap 4.7uF 10% 6.3V X5R 0402: Tolerance: TOL; User Part Number: PART#
C18 C19 = Cap 22NF 10% 16V 0402: Tolerance: TOL; User Part Number: PART#; signal model: CAP_22NF_10%_16V_0402_0402_22NF_22nF
C20 C21 = CAP 0.01UF 16V X7R 0402: Tolerance: TOL; User Part Number: PART#
C22 C23 C59 = Cap 4.7nF 10% 50V 0402: Tolerance: TOL; User Part Number: PART#
C24 C25 = Cap 2200PF 10% 50V 0402: Tolerance: TOL; User Part Number: PART#
C28 C36 C38 C39 C194 C221-C223 = CAP 1.0UF 10% 10V 0402
C60 C61 C97-C99 C105 C112 C208 C216 C251 = CAP: Tolerance: TOL; User Part Number: PART#
C87 C89 = Cap 18PF 5% 50V 0402: Tolerance: TOL; User Part Number: PART#
C90 C92 C93 C111 C116 C124 C144-C149 C155 C156 C206 C224-C231 C233-C239 = Cap 0.1UF +/-10% 10V 0402
C94 = PCAP: User Part Number: PART#; Tolerance: TOL
C96 C119 C120 C174-C176 C207 C249 = CAP 1.0UF 10% 10V 0402: Tolerance: TOL; User Part Number: PART#
C196 = Cap 4.7uF 10% 6.3V X5R 0402
C232 = CAP: User Part Number: *; Tolerance: *
D1 D2 = 82401646: User Part Number: *
D3-D11 = LED_WURTH_1
J1 J2 = FCC CONN_1
J3 = FFC_CONN_0
J4 = HDMI 19-Pin Receptacle: Tolerance: XXX; User Part Number: XXX
J5 = USB MINI-B
J6 J7 = 2x5: User Part Number: *; Tolerance: *
J8 J9 = 2x6 PMOD
J10 = Jack-DC
J11 = HEADER, 1x3-PIN: User Part Number: *
J12 J13 = 2x10
J14 = Header_3
L1-L4 = IND 10uH 245mA 0.82ohm 0806 SMD
L5 L6 L9 = IND Ferrite 0402 300mA/220: Tolerance: TOL; User Part Number: PART#
L7 L8 = INDUCTOR
R1 R2 R7-R12 R17 R19 R21-R25 R27-R30 R32 R34 R35 R61 R64 R94 R111 R112 R117 R123-R126 R129-R136 R138 R140-R152 R180-R182 R184 R185 R189-R192 R195 R196 R198 R199 R202-R204 R206-R217 R221 R223 R227 R229-R233 R235 R239-R243 R248-R250 R255 R257 R264 R267 R269-R271 R273-R277 R279-R286 R290 R291 R294 R302 R304 R307 R312-R314 = RESISTOR: Tolerance: TOL; User Part Number: PART#
R18 R20 R36-R39 R43 R45-R49 R51 R52 R55 R57-R60 R63 R66 R67 R71 R72 R77-R80 R85-R87 R93 R95 R102 R103 R106 R107 R110 R153-R155 R162 R165-R170 R272 = RES 100 OHM 1.0% 1/16W 0402: Tolerance: TOL; User Part Number: PART#
R31 R137 R139 R205 = RES 4.7k OHM 5% 1/16W 0402: Tolerance: TOL; User Part Number: PART#
R33 = RES 4.7k OHM 5% 1/16W 0402: Tolerance: TOL; User Part Number: PART#; signal model: RES_4.7K_OHM_5%_1/16W_0402_04_1_DNI
R40-R42 R44 R50 R53 R54 R56 R62 R65 R183 R186-R188 R193 R200 = R: Tolerance: TOL; User Part Number: PART#; signal model: R_0402_150_150
R68 R89 R91 R92 R98-R101 R114 R115 R118-R122 R127 R128 R179 R244 R245 R268 R303 R305 R306 R308 R309 = RES 2.0K OHM 1/16W 1% 0402 SMD: Tolerance: TOL; User Part Number: PART#
R73-R76 R81-R84 R88 R90 R96 R97 R104 R105 R108 R109 R156-R161 R163 R164 R171-R178 = RESISTOR: Tolerance: TOL; User Part Number: PART#; signal model: RESISTOR_0402_200_200
R113 R116 R194 R278 = R: Tolerance: TOL; User Part Number: PART#
R222 R228 R236 R238 R246 R247 R253 R254 R258 R260 R289 R292 R293 R315 = RESISTOR
R224 R226 = RES 16.5K OHM 1/10W 1% 0402: Tolerance: TOL; User Part Number: PART#
R225 = RES 10 OHM 1.0% 1/16W 0402: Tolerance: TOL; User Part Number: PART#
R252 = RES 30.1K OHM 1% 1/16W 0402 SMD: Tolerance: TOL; User Part Number: PART#
S1-S4 S6 S7 = TS-A02SA-2-S100
SW1 SW2 = SPST4
SW3 = SW-PUSH_3
TP1-TP8 TP10 TP11 TP13-TP16 TP19-TP22 TP25-TP28 TP31-TP34 TP45 TP48 TP50 TP54 TP57 TP60 TP63 TP66-TP68 = T POINT R
U1 = 10M50DAF484_v2.0_4.5
U2 = LPDDR2_IS43LD16640A-3BL_2
U3 = ADV7513BSWZ
U4 = EPM1270M256_2: Tolerance: *; User Part Number: *
U5 = MAX811: User Part Number: PART#; Tolerance: TOL
U6 = TPD2EUSB30: User Part Number: *; Tolerance: *
U7 = CY7C68013A_56QFN: User Part Number: *
U8-U11 = 824013
U14 = Clock Gen, Si5338A_CUSTOM, A5SK: User Part Number: *
U15 = Si510-DualCMOS: Tolerance: ?; User Part Number: XOS006RM01A
U16 = FDMC8878_VER2: User Part Number: *
U17 U21 = EN5329/5339QI_0
U18 = LTC4218CGN
U19 U22 = EP5348UI_0: Tolerance: ?
U20 = EP5358xUI
U23 = N25Q00AA13GSF40F_1
V1 V2 = SENSE_PAD: User Part Number: *
Y1 = CRYSTAL_SM_13: User Part Number: *
Y2 = XTAL 25MHz 30PPM 18pF mini: User Part Number: *

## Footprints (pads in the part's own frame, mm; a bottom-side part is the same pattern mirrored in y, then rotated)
10-89-1141
  rect 1.524x1.524 hole 1.016: 1(0,0)
  round 1.524 hole 1.016: 2(2.54,0) 3(0,-2.54) 4(2.54,-2.54) 5(0,-5.08) 6(2.54,-5.08) 7(0,-7.62) 8(2.54,-7.62) 9(0,-10.16) 10(2.54,-10.16) 11(0,-12.7) 12(2.54,-12.7) 13(0,-15.24) 14(2.54,-15.24)
10-89-1201
  rect 1.6x1.6 hole 1: 1(0,0)
  round 1.6 hole 1: 2(0,2.54) 3(2.54,0) 4(2.54,2.54) 5(5.08,0) 6(5.08,2.54) 7(7.62,0) 8(7.62,2.54) 9(10.16,0) 10(10.16,2.54) 11(12.7,0) 12(12.7,2.54) 13(15.24,0) 14(15.24,2.54) 15(17.78,0) 16(17.78,2.54) 17(20.32,0) 18(20.32,2.54) 19(22.86,0) 20(22.86,2.54)
16-LEAD_PLASTIC_SSOP
  oval 0.356x2.032 smd: 1(-2.223,-2.6) 2(-1.587,-2.6) 3(-0.953,-2.6) 4(-0.318,-2.6) 5(0.318,-2.6) 6(0.953,-2.6) 7(1.587,-2.6) 8(2.223,-2.6) 9(2.223,2.6) 10(1.587,2.6) 11(0.953,2.6) 12(0.318,2.6) 13(-0.318,2.6) 14(-0.953,2.6) 15(-1.587,2.6) 16(-2.223,2.6)
0402
  rect 0.508x0.508 smd: 1(0,0.445) 2(0,-0.445)
0603
  rect 1.016x1.168 smd: 1(-0.889,0) 2(0.889,0)
0805
  rect 1.27x1.473 smd: 1(-0.953,0) 2(0.953,0)
0806
  rect 1.27x1.524 smd: 1(0,1.016) 2(0,-1.016)
1206
  rect 1.6x1.905 smd: 1(-1.397,0) 2(1.397,0)
1210
  rect 1.27x2.794 smd: 1(-1.524,0) 2(1.524,0)
7343P
  rect 2.489x2.591 smd: 1(-3.302,0) 2(3.302,0)
52559-3652
  rect 0.6x1.524 smd: 1(-8.75,-1.4) 2(-8.25,1.4) 3(-7.75,-1.4) 4(-7.25,1.4) 5(-6.75,-1.4) 6(-6.25,1.4) 7(-5.75,-1.4) 8(-5.25,1.4) 9(-4.75,-1.4) 10(-4.25,1.4) 11(-3.75,-1.4) 12(-3.25,1.4) 13(-2.75,-1.4) 14(-2.25,1.4) 15(-1.75,-1.4) 16(-1.25,1.4) 17(-0.75,-1.4) 18(-0.25,1.4) 19(0.25,-1.4) 20(0.75,1.4) 21(1.25,-1.4) 22(1.75,1.4) 23(2.25,-1.4) 24(2.75,1.4) 25(3.25,-1.4) 26(3.75,1.4) 27(4.25,-1.4) 28(4.75,1.4) 29(5.25,-1.4) 30(5.75,1.4) 31(6.25,-1.4) 32(6.75,1.4) 33(7.25,-1.4) 34(7.75,1.4) 35(8.25,-1.4) 36(8.75,1.4)
  rect 0.813x1.524 smd: G1(-9.75,-1.4) G2(9.75,-1.4) G3(9.75,1.4) G4(-9.75,1.4)
68711614522
  rect 0.279x1.397 smd: 1(-3.75,0) 2(-3.25,0) 3(-2.75,0) 4(-2.25,0) 5(-1.75,0) 6(-1.25,0) 7(-0.75,0) 8(-0.25,0) 9(0.25,0) 10(0.75,0) 11(1.25,0) 12(1.75,0) 13(2.25,0) 14(2.75,0) 15(3.25,0) 16(3.75,0)
  rect 2.718x3.048 smd: 17(-5.68,-1.9) 18(5.68,-1.9)
C0402_BGA
  rrect 0.635x0.635 smd: 1(-0.5,0) 2(0.5,0)
CONN_TSW_103_07_L_S
  rect 1.651x1.651 hole 1.143: 1(0,0)
  round 1.651 hole 1.143: 2(2.54,0) 3(5.08,0)
DIPSWITCH_SMT_QUAD
  rect 0.762x1.27 smd: 1(0,-3.81) 2(1.27,-3.81) 3(2.54,-3.81) 4(3.81,-3.81) 5(3.81,3.81) 6(2.54,3.81) 7(1.27,3.81) 8(0,3.81)
DRT
  rect 0.305x0.305 smd: 1(-0.35,-0.425) 2(0.35,-0.425) 3(0,0.425)
EN5339QI
  oval 0.813x0.356 smd: 1(-3,0.975) 2(-3,0.325) 3(-3,-0.325) 4(-3,-0.975) 13(3,-0.975) 14(3,-0.325) 15(3,0.325) 16(3,0.975)
  oval 0.356x0.813 smd: 5(-2.275,-2) 6(-1.625,-2) 7(-0.975,-2) 8(-0.325,-2) 9(0.325,-2) 10(0.975,-2) 11(1.625,-2) 12(2.275,-2) 17(2.275,2) 18(1.625,2) 19(0.975,2) 20(0.325,2) 21(-0.325,2) 22(-0.975,2) 23(-1.625,2) 24(-2.275,2)
  rect 1.905x0.914 smd: 25(-1.3,0.1)
  rect 2.261x1.803 smd: 26(1.125,-0.35)
EP5348UI
  rect 0.55x0.2 smd: 1(-0.8,0.8) 2(-0.8,0.4) 3(-0.8,0) 4(-0.8,-0.4) 5(-0.8,-0.8) 8(0.8,-0.8) 9(0.8,-0.4) 10(0.8,0) 11(0.8,0.4) 12(0.8,0.8)
  rect 0.2x0.55 smd: 6(-0.2,-0.925) 7(0.2,-0.925) 13(0.2,0.925) 14(-0.2,0.925)
F484
  round 0.48 smd: A1(-10.5,10.5) A2(-9.5,10.5) A3(-8.5,10.5) A4(-7.5,10.5) A5(-6.5,10.5) A6(-5.5,10.5) A7(-4.5,10.5) A8(-3.5,10.5) A9(-2.5,10.5) A10(-1.5,10.5) A11(-0.5,10.5) A12(0.5,10.5) A13(1.5,10.5) A14(2.5,10.5) A15(3.5,10.5) A16(4.5,10.5) A17(5.5,10.5) A18(6.5,10.5) A19(7.5,10.5) A20(8.5,10.5) A21(9.5,10.5) A22(10.5,10.5) AA1(-10.5,-9.5) AA2(-9.5,-9.5) AA3(-8.5,-9.5) AA4(-7.5,-9.5) AA5(-6.5,-9.5) AA6(-5.5,-9.5) AA7(-4.5,-9.5) AA8(-3.5,-9.5) AA9(-2.5,-9.5) AA10(-1.5,-9.5) AA11(-0.5,-9.5) AA12(0.5,-9.5) AA13(1.5,-9.5) AA14(2.5,-9.5) AA15(3.5,-9.5) AA16(4.5,-9.5) AA17(5.5,-9.5) AA18(6.5,-9.5) AA19(7.5,-9.5) AA20(8.5,-9.5) AA21(9.5,-9.5) AA22(10.5,-9.5) AB1(-10.5,-10.5) AB2(-9.5,-10.5) AB3(-8.5,-10.5) AB4(-7.5,-10.5) AB5(-6.5,-10.5) AB6(-5.5,-10.5) AB7(-4.5,-10.5) AB8(-3.5,-10.5) AB9(-2.5,-10.5) AB10(-1.5,-10.5) AB11(-0.5,-10.5) AB12(0.5,-10.5) AB13(1.5,-10.5) AB14(2.5,-10.5) AB15(3.5,-10.5) AB16(4.5,-10.5) AB17(5.5,-10.5) AB18(6.5,-10.5) AB19(7.5,-10.5) AB20(8.5,-10.5) AB21(9.5,-10.5) AB22(10.5,-10.5) B1(-10.5,9.5) B2(-9.5,9.5) B3(-8.5,9.5) B4(-7.5,9.5) B5(-6.5,9.5) B6(-5.5,9.5) B7(-4.5,9.5) B8(-3.5,9.5) B9(-2.5,9.5) B10(-1.5,9.5) B11(-0.5,9.5) B12(0.5,9.5) B13(1.5,9.5) B14(2.5,9.5) B15(3.5,9.5) B16(4.5,9.5) B17(5.5,9.5) B18(6.5,9.5) B19(7.5,9.5) B20(8.5,9.5) B21(9.5,9.5) B22(10.5,9.5) C1(-10.5,8.5) C2(-9.5,8.5) C3(-8.5,8.5) C4(-7.5,8.5) C5(-6.5,8.5) C6(-5.5,8.5) C7(-4.5,8.5) C8(-3.5,8.5) C9(-2.5,8.5) C10(-1.5,8.5) C11(-0.5,8.5) C12(0.5,8.5) C13(1.5,8.5) C14(2.5,8.5) C15(3.5,8.5) C16(4.5,8.5) C17(5.5,8.5) C18(6.5,8.5) C19(7.5,8.5) C20(8.5,8.5) C21(9.5,8.5) C22(10.5,8.5) D1(-10.5,7.5) D2(-9.5,7.5) D3(-8.5,7.5) D4(-7.5,7.5) D5(-6.5,7.5) D6(-5.5,7.5) D7(-4.5,7.5) D8(-3.5,7.5) D9(-2.5,7.5) D10(-1.5,7.5) D11(-0.5,7.5) D12(0.5,7.5) D13(1.5,7.5) D14(2.5,7.5) D15(3.5,7.5) D16(4.5,7.5) D17(5.5,7.5) D18(6.5,7.5) D19(7.5,7.5) D20(8.5,7.5) D21(9.5,7.5) D22(10.5,7.5) E1(-10.5,6.5) E2(-9.5,6.5) E3(-8.5,6.5) E4(-7.5,6.5) E5(-6.5,6.5) E6(-5.5,6.5) E7(-4.5,6.5) E8(-3.5,6.5) E9(-2.5,6.5) E10(-1.5,6.5) E11(-0.5,6.5) E12(0.5,6.5) E13(1.5,6.5) E14(2.5,6.5) E15(3.5,6.5) E16(4.5,6.5) E17(5.5,6.5) E18(6.5,6.5) E19(7.5,6.5) E20(8.5,6.5) E21(9.5,6.5) E22(10.5,6.5) F1(-10.5,5.5) F2(-9.5,5.5) F3(-8.5,5.5) F4(-7.5,5.5) F5(-6.5,5.5) F6(-5.5,5.5) F7(-4.5,5.5) F8(-3.5,5.5) F9(-2.5,5.5) F10(-1.5,5.5) F11(-0.5,5.5) F12(0.5,5.5) F13(1.5,5.5) F14(2.5,5.5) F15(3.5,5.5) F16(4.5,5.5) F17(5.5,5.5) F18(6.5,5.5) F19(7.5,5.5) F20(8.5,5.5) F21(9.5,5.5) F22(10.5,5.5) G1(-10.5,4.5) G2(-9.5,4.5) G3(-8.5,4.5) G4(-7.5,4.5) G5(-6.5,4.5) G6(-5.5,4.5) G7(-4.5,4.5) G8(-3.5,4.5) G9(-2.5,4.5) G10(-1.5,4.5) G11(-0.5,4.5) G12(0.5,4.5) G13(1.5,4.5) G14(2.5,4.5) G15(3.5,4.5) G16(4.5,4.5) G17(5.5,4.5) G18(6.5,4.5) G19(7.5,4.5) G20(8.5,4.5) G21(9.5,4.5) G22(10.5,4.5) H1(-10.5,3.5) H2(-9.5,3.5) H3(-8.5,3.5) H4(-7.5,3.5) H5(-6.5,3.5) H6(-5.5,3.5) H7(-4.5,3.5) H8(-3.5,3.5) H9(-2.5,3.5) H10(-1.5,3.5) H11(-0.5,3.5) H12(0.5,3.5) H13(1.5,3.5) H14(2.5,3.5) H15(3.5,3.5) H16(4.5,3.5) H17(5.5,3.5) H18(6.5,3.5) H19(7.5,3.5) H20(8.5,3.5) H21(9.5,3.5) H22(10.5,3.5) J1(-10.5,2.5) J2(-9.5,2.5) J3(-8.5,2.5) J4(-7.5,2.5) J5(-6.5,2.5) J6(-5.5,2.5) J7(-4.5,2.5) J8(-3.5,2.5) J9(-2.5,2.5) J10(-1.5,2.5) J11(-0.5,2.5) J12(0.5,2.5) J13(1.5,2.5) J14(2.5,2.5) J15(3.5,2.5) J16(4.5,2.5) J17(5.5,2.5) J18(6.5,2.5) J19(7.5,2.5) J20(8.5,2.5) J21(9.5,2.5) J22(10.5,2.5) K1(-10.5,1.5) K2(-9.5,1.5) K3(-8.5,1.5) K4(-7.5,1.5) K5(-6.5,1.5) K6(-5.5,1.5) K7(-4.5,1.5) K8(-3.5,1.5) K9(-2.5,1.5) K10(-1.5,1.5) K11(-0.5,1.5) K12(0.5,1.5) K13(1.5,1.5) K14(2.5,1.5) K15(3.5,1.5) K16(4.5,1.5) K17(5.5,1.5) K18(6.5,1.5) K19(7.5,1.5) K20(8.5,1.5) K21(9.5,1.5) K22(10.5,1.5) L1(-10.5,0.5) L2(-9.5,0.5) L3(-8.5,0.5) L4(-7.5,0.5) L5(-6.5,0.5) L6(-5.5,0.5) L7(-4.5,0.5) L8(-3.5,0.5) L9(-2.5,0.5) L10(-1.5,0.5) L11(-0.5,0.5) L12(0.5,0.5) L13(1.5,0.5) L14(2.5,0.5) L15(3.5,0.5) L16(4.5,0.5) L17(5.5,0.5) L18(6.5,0.5) L19(7.5,0.5) L20(8.5,0.5) L21(9.5,0.5) L22(10.5,0.5) M1(-10.5,-0.5) M2(-9.5,-0.5) M3(-8.5,-0.5) M4(-7.5,-0.5) M5(-6.5,-0.5) M6(-5.5,-0.5) M7(-4.5,-0.5) M8(-3.5,-0.5) M9(-2.5,-0.5) M10(-1.5,-0.5) M11(-0.5,-0.5) M12(0.5,-0.5) M13(1.5,-0.5) M14(2.5,-0.5) M15(3.5,-0.5) M16(4.5,-0.5) M17(5.5,-0.5) M18(6.5,-0.5) M19(7.5,-0.5) M20(8.5,-0.5) M21(9.5,-0.5) M22(10.5,-0.5) N1(-10.5,-1.5) N2(-9.5,-1.5) N3(-8.5,-1.5) N4(-7.5,-1.5) N5(-6.5,-1.5) N6(-5.5,-1.5) N7(-4.5,-1.5) N8(-3.5,-1.5) N9(-2.5,-1.5) N10(-1.5,-1.5) N11(-0.5,-1.5) N12(0.5,-1.5) N13(1.5,-1.5) N14(2.5,-1.5) N15(3.5,-1.5) N16(4.5,-1.5) N17(5.5,-1.5) N18(6.5,-1.5) N19(7.5,-1.5) N20(8.5,-1.5) N21(9.5,-1.5) N22(10.5,-1.5) P1(-10.5,-2.5) P2(-9.5,-2.5) P3(-8.5,-2.5) P4(-7.5,-2.5) P5(-6.5,-2.5) P6(-5.5,-2.5) P7(-4.5,-2.5) P8(-3.5,-2.5) P9(-2.5,-2.5) P10(-1.5,-2.5) P11(-0.5,-2.5) P12(0.5,-2.5) P13(1.5,-2.5) P14(2.5,-2.5) P15(3.5,-2.5) P16(4.5,-2.5) P17(5.5,-2.5) P18(6.5,-2.5) P19(7.5,-2.5) P20(8.5,-2.5) P21(9.5,-2.5) P22(10.5,-2.5) R1(-10.5,-3.5) R2(-9.5,-3.5) R3(-8.5,-3.5) R4(-7.5,-3.5) R5(-6.5,-3.5) R6(-5.5,-3.5) R7(-4.5,-3.5) R8(-3.5,-3.5) R9(-2.5,-3.5) R10(-1.5,-3.5) R11(-0.5,-3.5) R12(0.5,-3.5) R13(1.5,-3.5) R14(2.5,-3.5) R15(3.5,-3.5) R16(4.5,-3.5) R17(5.5,-3.5) R18(6.5,-3.5) R19(7.5,-3.5) R20(8.5,-3.5) R21(9.5,-3.5) R22(10.5,-3.5) T1(-10.5,-4.5) T2(-9.5,-4.5) T3(-8.5,-4.5) T4(-7.5,-4.5) T5(-6.5,-4.5) T6(-5.5,-4.5) T7(-4.5,-4.5) T8(-3.5,-4.5) T9(-2.5,-4.5) T10(-1.5,-4.5) T11(-0.5,-4.5) T12(0.5,-4.5) T13(1.5,-4.5) T14(2.5,-4.5) T15(3.5,-4.5) T16(4.5,-4.5) T17(5.5,-4.5) T18(6.5,-4.5) T19(7.5,-4.5) T20(8.5,-4.5) T21(9.5,-4.5) T22(10.5,-4.5) U1(-10.5,-5.5) U2(-9.5,-5.5) U3(-8.5,-5.5) U4(-7.5,-5.5) U5(-6.5,-5.5) U6(-5.5,-5.5) U7(-4.5,-5.5) U8(-3.5,-5.5) U9(-2.5,-5.5) U10(-1.5,-5.5) U11(-0.5,-5.5) U12(0.5,-5.5) U13(1.5,-5.5) U14(2.5,-5.5) U15(3.5,-5.5) U16(4.5,-5.5) U17(5.5,-5.5) U18(6.5,-5.5) U19(7.5,-5.5) U20(8.5,-5.5) U21(9.5,-5.5) U22(10.5,-5.5) V1(-10.5,-6.5) V2(-9.5,-6.5) V3(-8.5,-6.5) V4(-7.5,-6.5) V5(-6.5,-6.5) V6(-5.5,-6.5) V7(-4.5,-6.5) V8(-3.5,-6.5) V9(-2.5,-6.5) V10(-1.5,-6.5) V11(-0.5,-6.5) V12(0.5,-6.5) V13(1.5,-6.5) V14(2.5,-6.5) V15(3.5,-6.5) V16(4.5,-6.5) V17(5.5,-6.5) V18(6.5,-6.5) V19(7.5,-6.5) V20(8.5,-6.5) V21(9.5,-6.5) V22(10.5,-6.5) W1(-10.5,-7.5) W2(-9.5,-7.5) W3(-8.5,-7.5) W4(-7.5,-7.5) W5(-6.5,-7.5) W6(-5.5,-7.5) W7(-4.5,-7.5) W8(-3.5,-7.5) W9(-2.5,-7.5) W10(-1.5,-7.5) W11(-0.5,-7.5) W12(0.5,-7.5) W13(1.5,-7.5) W14(2.5,-7.5) W15(3.5,-7.5) W16(4.5,-7.5) W17(5.5,-7.5) W18(6.5,-7.5) W19(7.5,-7.5) W20(8.5,-7.5) W21(9.5,-7.5) W22(10.5,-7.5) Y1(-10.5,-8.5) Y2(-9.5,-8.5) Y3(-8.5,-8.5) Y4(-7.5,-8.5) Y5(-6.5,-8.5) Y6(-5.5,-8.5) Y7(-4.5,-8.5) Y8(-3.5,-8.5) Y9(-2.5,-8.5) Y10(-1.5,-8.5) Y11(-0.5,-8.5) Y12(0.5,-8.5) Y13(1.5,-8.5) Y14(2.5,-8.5) Y15(3.5,-8.5) Y16(4.5,-8.5) Y17(5.5,-8.5) Y18(6.5,-8.5) Y19(7.5,-8.5) Y20(8.5,-8.5) Y21(9.5,-8.5) Y22(10.5,-8.5)
FBGA134
  round 0.3 smd: A1(-2.925,5.2) A2(-2.275,5.2) A9(2.275,5.2) A10(2.925,5.2) B1(-2.925,4.55) B2(-2.275,4.55) B3(-1.625,4.55) B5(-0.325,4.55) B6(0.325,4.55) B7(0.975,4.55) B8(1.625,4.55) B9(2.275,4.55) B10(2.925,4.55) C1(-2.925,3.9) C2(-2.275,3.9) C3(-1.625,3.9) C5(-0.325,3.9) C6(0.325,3.9) C7(0.975,3.9) C8(1.625,3.9) C9(2.275,3.9) C10(2.925,3.9) D1(-2.925,3.25) D2(-2.275,3.25) D3(-1.625,3.25) D5(-0.325,3.25) D6(0.325,3.25) D7(0.975,3.25) D8(1.625,3.25) D9(2.275,3.25) D10(2.925,3.25) E1(-2.925,2.6) E2(-2.275,2.6) E3(-1.625,2.6) E5(-0.325,2.6) E6(0.325,2.6) E7(0.975,2.6) E8(1.625,2.6) E9(2.275,2.6) E10(2.925,2.6) F1(-2.925,1.95) F2(-2.275,1.95) F3(-1.625,1.95) F5(-0.325,1.95) F6(0.325,1.95) F7(0.975,1.95) F8(1.625,1.95) F9(2.275,1.95) F10(2.925,1.95) G1(-2.925,1.3) G2(-2.275,1.3) G3(-1.625,1.3) G5(-0.325,1.3) G6(0.325,1.3) G7(0.975,1.3) G8(1.625,1.3) G9(2.275,1.3) G10(2.925,1.3) H1(-2.925,0.65) H2(-2.275,0.65) H3(-1.625,0.65) H5(-0.325,0.65) H6(0.325,0.65) J1(-2.925,0) J2(-2.275,0) J3(-1.625,0) J5(-0.325,0) J6(0.325,0) J7(0.975,0) J8(1.625,0) J9(2.275,0) K1(-2.925,-0.65) K2(-2.275,-0.65) K3(-1.625,-0.65) K5(-0.325,-0.65) K6(0.325,-0.65) L1(-2.925,-1.3) L2(-2.275,-1.3) L3(-1.625,-1.3) L5(-0.325,-1.3) L6(0.325,-1.3) L7(0.975,-1.3) L8(1.625,-1.3) L9(2.275,-1.3) L10(2.925,-1.3) M1(-2.925,-1.95) M2(-2.275,-1.95) M3(-1.625,-1.95) M5(-0.325,-1.95) M6(0.325,-1.95) M7(0.975,-1.95) M8(1.625,-1.95) M9(2.275,-1.95) M10(2.925,-1.95) N1(-2.925,-2.6) N2(-2.275,-2.6) N3(-1.625,-2.6) N5(-0.325,-2.6) N6(0.325,-2.6) N7(0.975,-2.6) N8(1.625,-2.6) N9(2.275,-2.6) N10(2.925,-2.6) P1(-2.925,-3.25) P2(-2.275,-3.25) P3(-1.625,-3.25) P5(-0.325,-3.25) P6(0.325,-3.25) P7(0.975,-3.25) P8(1.625,-3.25) P9(2.275,-3.25) P10(2.925,-3.25) R1(-2.925,-3.9) R2(-2.275,-3.9) R3(-1.625,-3.9) R5(-0.325,-3.9) R6(0.325,-3.9) R7(0.975,-3.9) R8(1.625,-3.9) R9(2.275,-3.9) R10(2.925,-3.9) T1(-2.925,-4.55) T2(-2.275,-4.55) T3(-1.625,-4.55) T5(-0.325,-4.55) T6(0.325,-4.55) T7(0.975,-4.55) T8(1.625,-4.55) T9(2.275,-4.55) T10(2.925,-4.55) U1(-2.925,-5.2) U2(-2.275,-5.2) U9(2.275,-5.2) U10(2.925,-5.2)
FDMC8878_VER2
  rect 0.432x0.889 smd: 1(-0.975,-1.325) 2(-0.325,-1.325) 3(0.325,-1.325) 4(0.975,-1.325)
  custom 0.542x0.542 smd: 5(0,0.685)
HDMI-19PIN
  rect 2.337x0.279 smd: 1(0,-4.5) 2(0,-4) 3(0,-3.5) 4(0,-3) 5(0,-2.5) 6(0,-2) 7(0,-1.5) 8(0,-1) 9(0,-0.5) 10(0,0) 11(0,0.5) 12(0,1) 13(0,1.5) 14(0,2) 15(0,2.5) 16(0,3) 17(0,3.5) 18(0,4) 19(0,4.5)
  oval 2.743x1.524 hole 2.108x0.889: G1(-6.595,-7.25) G3(-6.595,7.25)
  oval 3.302x1.524 hole 2.692x0.889: G2(-0.625,-7.25) G4(-0.625,7.25)
HDR2X5_100MIL_SMT
  rect 3.175x1.27 smd: 1(-2.731,7.62) 2(2.731,7.62) 3(-2.731,5.08) 4(2.731,5.08) 5(-2.731,2.54) 6(2.731,2.54) 7(-2.731,0) 8(2.731,0) 9(-2.731,-2.54) 10(2.731,-2.54)
HDR2X6_100MIL
  rect 1.524x1.524 hole 1.016: 1(0,0)
  round 1.524 hole 1.016: 2(0,-2.54) 3(0,-5.08) 4(0,-7.62) 5(0,-10.16) 6(0,-12.7) 7(2.54,0) 8(2.54,-2.54) 9(2.54,-5.08) 10(2.54,-7.62) 11(2.54,-10.16) 12(2.54,-12.7)
JACK-DC_2MM
  oval 4.267x1.397 hole 3.505x0.787: 1(0,0) 2(0,-6.2)
  oval 1.397x4.267 hole 0.787x3.505: 3(-4.7,-3)
LED_0603
  rect 0.787x0.991 smd: 1(-0.813,0) 2(0.813,0)
LQFP-64
  oval 1.8x0.28 smd: 1(-5.7,3.75) 2(-5.7,3.25) 3(-5.7,2.75) 4(-5.7,2.25) 5(-5.7,1.75) 6(-5.7,1.25) 7(-5.7,0.75) 8(-5.7,0.25) 9(-5.7,-0.25) 10(-5.7,-0.75) 11(-5.7,-1.25) 12(-5.7,-1.75) 13(-5.7,-2.25) 14(-5.7,-2.75) 15(-5.7,-3.25) 16(-5.7,-3.75) 33(5.7,-3.75) 34(5.7,-3.25) 35(5.7,-2.75) 36(5.7,-2.25) 37(5.7,-1.75) 38(5.7,-1.25) 39(5.7,-0.75) 40(5.7,-0.25) 41(5.7,0.25) 42(5.7,0.75) 43(5.7,1.25) 44(5.7,1.75) 45(5.7,2.25) 46(5.7,2.75) 47(5.7,3.25) 48(5.7,3.75)
  oval 0.28x1.8 smd: 17(-3.75,-5.7) 18(-3.25,-5.7) 19(-2.75,-5.7) 20(-2.25,-5.7) 21(-1.75,-5.7) 22(-1.25,-5.7) 23(-0.75,-5.7) 24(-0.25,-5.7) 25(0.25,-5.7) 26(0.75,-5.7) 27(1.25,-5.7) 28(1.75,-5.7) 29(2.25,-5.7) 30(2.75,-5.7) 31(3.25,-5.7) 32(3.75,-5.7) 49(3.75,5.7) 50(3.25,5.7) 51(2.75,5.7) 52(2.25,5.7) 53(1.75,5.7) 54(1.25,5.7) 55(0.75,5.7) 56(0.25,5.7) 57(-0.25,5.7) 58(-0.75,5.7) 59(-1.25,5.7) 60(-1.75,5.7) 61(-2.25,5.7) 62(-2.75,5.7) 63(-3.25,5.7) 64(-3.75,5.7)
  rect 5.2x5.2 smd: 65(0,0)
M256
  round 0.25 smd: A1(-4.75,4.75) A2(-4.25,4.75) A3(-3.75,4.75) A4(-3.25,4.75) A5(-2.75,4.75) A6(-2.25,4.75) A7(-1.75,4.75) A8(-1.25,4.75) A9(-0.75,4.75) A10(-0.25,4.75) A11(0.25,4.75) A12(0.75,4.75) A13(1.25,4.75) A14(1.75,4.75) A15(2.25,4.75) A16(2.75,4.75) A17(3.25,4.75) A18(3.75,4.75) A19(4.25,4.75) A20(4.75,4.75) B1(-4.75,4.25) B2(-4.25,4.25) B3(-3.75,4.25) B4(-3.25,4.25) B5(-2.75,4.25) B6(-2.25,4.25) B7(-1.75,4.25) B8(-1.25,4.25) B9(-0.75,4.25) B10(-0.25,4.25) B11(0.25,4.25) B12(0.75,4.25) B13(1.25,4.25) B14(1.75,4.25) B15(2.25,4.25) B16(2.75,4.25) B17(3.25,4.25) B18(3.75,4.25) B19(4.25,4.25) B20(4.75,4.25) C1(-4.75,3.75) C2(-4.25,3.75) C3(-3.75,3.75) C4(-3.25,3.75) C5(-2.75,3.75) C6(-2.25,3.75) C7(-1.75,3.75) C8(-1.25,3.75) C9(-0.75,3.75) C10(-0.25,3.75) C11(0.25,3.75) C12(0.75,3.75) C13(1.25,3.75) C14(1.75,3.75) C15(2.25,3.75) C16(2.75,3.75) C17(3.25,3.75) C18(3.75,3.75) C19(4.25,3.75) C20(4.75,3.75) D1(-4.75,3.25) D2(-4.25,3.25) D3(-3.75,3.25) D4(-3.25,3.25) D5(-2.75,3.25) D6(-2.25,3.25) D7(-1.75,3.25) D8(-1.25,3.25) D9(-0.75,3.25) D10(-0.25,3.25) D11(0.25,3.25) D12(0.75,3.25) D13(1.25,3.25) D14(1.75,3.25) D15(2.25,3.25) D16(2.75,3.25) D17(3.25,3.25) D18(3.75,3.25) D19(4.25,3.25) D20(4.75,3.25) E1(-4.75,2.75) E2(-4.25,2.75) E3(-3.75,2.75) E4(-3.25,2.75) E17(3.25,2.75) E18(3.75,2.75) E19(4.25,2.75) E20(4.75,2.75) F1(-4.75,2.25) F2(-4.25,2.25) F3(-3.75,2.25) F4(-3.25,2.25) F17(3.25,2.25) F18(3.75,2.25) F19(4.25,2.25) F20(4.75,2.25) G1(-4.75,1.75) G2(-4.25,1.75) G3(-3.75,1.75) G4(-3.25,1.75) G17(3.25,1.75) G18(3.75,1.75) G19(4.25,1.75) G20(4.75,1.75) H1(-4.75,1.25) H2(-4.25,1.25) H3(-3.75,1.25) H4(-3.25,1.25) H17(3.25,1.25) H18(3.75,1.25) H19(4.25,1.25) H20(4.75,1.25) J1(-4.75,0.75) J2(-4.25,0.75) J3(-3.75,0.75) J4(-3.25,0.75) J17(3.25,0.75) J18(3.75,0.75) J19(4.25,0.75) J20(4.75,0.75) K1(-4.75,0.25) K2(-4.25,0.25) K3(-3.75,0.25) K4(-3.25,0.25) K17(3.25,0.25) K18(3.75,0.25) K19(4.25,0.25) K20(4.75,0.25) L1(-4.75,-0.25) L2(-4.25,-0.25) L3(-3.75,-0.25) L4(-3.25,-0.25) L17(3.25,-0.25) L18(3.75,-0.25) L19(4.25,-0.25) L20(4.75,-0.25) M1(-4.75,-0.75) M2(-4.25,-0.75) M3(-3.75,-0.75) M4(-3.25,-0.75) M17(3.25,-0.75) M18(3.75,-0.75) M19(4.25,-0.75) M20(4.75,-0.75) N1(-4.75,-1.25) N2(-4.25,-1.25) N3(-3.75,-1.25) N4(-3.25,-1.25) N17(3.25,-1.25) N18(3.75,-1.25) N19(4.25,-1.25) N20(4.75,-1.25) P1(-4.75,-1.75) P2(-4.25,-1.75) P3(-3.75,-1.75) P4(-3.25,-1.75) P17(3.25,-1.75) P18(3.75,-1.75) P19(4.25,-1.75) P20(4.75,-1.75) R1(-4.75,-2.25) R2(-4.25,-2.25) R3(-3.75,-2.25) R4(-3.25,-2.25) R17(3.25,-2.25) R18(3.75,-2.25) R19(4.25,-2.25) R20(4.75,-2.25) T1(-4.75,-2.75) T2(-4.25,-2.75) T3(-3.75,-2.75) T4(-3.25,-2.75) T17(3.25,-2.75) T18(3.75,-2.75) T19(4.25,-2.75) T20(4.75,-2.75) U1(-4.75,-3.25) U2(-4.25,-3.25) U3(-3.75,-3.25) U4(-3.25,-3.25) U5(-2.75,-3.25) U6(-2.25,-3.25) U7(-1.75,-3.25) U8(-1.25,-3.25) U9(-0.75,-3.25) U10(-0.25,-3.25) U11(0.25,-3.25) U12(0.75,-3.25) U13(1.25,-3.25) U14(1.75,-3.25) U15(2.25,-3.25) U16(2.75,-3.25) U17(3.25,-3.25) U18(3.75,-3.25) U19(4.25,-3.25) U20(4.75,-3.25) V1(-4.75,-3.75) V2(-4.25,-3.75) V3(-3.75,-3.75) V4(-3.25,-3.75) V5(-2.75,-3.75) V6(-2.25,-3.75) V7(-1.75,-3.75) V8(-1.25,-3.75) V9(-0.75,-3.75) V10(-0.25,-3.75) V11(0.25,-3.75) V12(0.75,-3.75) V13(1.25,-3.75) V14(1.75,-3.75) V15(2.25,-3.75) V16(2.75,-3.75) V17(3.25,-3.75) V18(3.75,-3.75) V19(4.25,-3.75) V20(4.75,-3.75) W1(-4.75,-4.25) W2(-4.25,-4.25) W3(-3.75,-4.25) W4(-3.25,-4.25) W5(-2.75,-4.25) W6(-2.25,-4.25) W7(-1.75,-4.25) W8(-1.25,-4.25) W9(-0.75,-4.25) W10(-0.25,-4.25) W11(0.25,-4.25) W12(0.75,-4.25) W13(1.25,-4.25) W14(1.75,-4.25) W15(2.25,-4.25) W16(2.75,-4.25) W17(3.25,-4.25) W18(3.75,-4.25) W19(4.25,-4.25) W20(4.75,-4.25) Y1(-4.75,-4.75) Y2(-4.25,-4.75) Y3(-3.75,-4.75) Y4(-3.25,-4.75) Y5(-2.75,-4.75) Y6(-2.25,-4.75) Y7(-1.75,-4.75) Y8(-1.25,-4.75) Y9(-0.75,-4.75) Y10(-0.25,-4.75) Y11(0.25,-4.75) Y12(0.75,-4.75) Y13(1.25,-4.75) Y14(1.75,-4.75) Y15(2.25,-4.75) Y16(2.75,-4.75) Y17(3.25,-4.75) Y18(3.75,-4.75) Y19(4.25,-4.75) Y20(4.75,-4.75)
PUSHBUTTON_SMT
  rect 2x1.4 smd: 1(-3.5,1.5) 2(3.5,1.5) 3(-3.5,-1.5) 4(3.5,-1.5)
QFN24
  oval 0.813x0.279 smd: 1(-1.95,1.25) 2(-1.95,0.75) 3(-1.95,0.25) 4(-1.95,-0.25) 5(-1.95,-0.75) 6(-1.95,-1.25) 13(1.95,-1.25) 14(1.95,-0.75) 15(1.95,-0.25) 16(1.95,0.25) 17(1.95,0.75) 18(1.95,1.25)
  oval 0.279x0.813 smd: 7(-1.25,-1.95) 8(-0.75,-1.95) 9(-0.25,-1.95) 10(0.25,-1.95) 11(0.75,-1.95) 12(1.25,-1.95) 19(1.25,1.95) 20(0.75,1.95) 21(0.25,1.95) 22(-0.25,1.95) 23(-0.75,1.95) 24(-1.25,1.95)
  rect 2.591x2.591 smd: 25(0,0)
